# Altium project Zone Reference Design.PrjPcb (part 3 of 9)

## Sheet Load Driver Overview.SchDoc
size 431 x 279 mm; Date: Not shown in title block; ApprovedBy: Not shown in title block; CheckedBy: Not shown in title block; Author: Not shown in title block; CompanyName: Not shown in title block; Engineer: Not shown in title block; Organization: Not shown in title block; Address1: Not shown in title block; Address2: Not shown in title block; Address3: Not shown in title block; Address4: Not shown in title block; DocumentNumber: 1; Revision: Use project parameter SCH_Rev; SheetNumber: 13; SheetTotal: 30; PageSetup: Record=PageOptions¦CenterHorizontal=True¦CenterVertical=True¦PrintScale=1.00¦XCorrection=1.00¦YCorrection=1.00¦PrintKind=0¦BorderSize=5000000¦LeftOffset=0¦BottomOffset=0¦Orientation=2¦PaperLength=1000¦PaperWidth=1000¦Scale=100¦PaperSource=15¦PrintQuality=600¦MediaType=1¦DitherType=10¦PaperKind=Letter¦PrintScaleMode=1
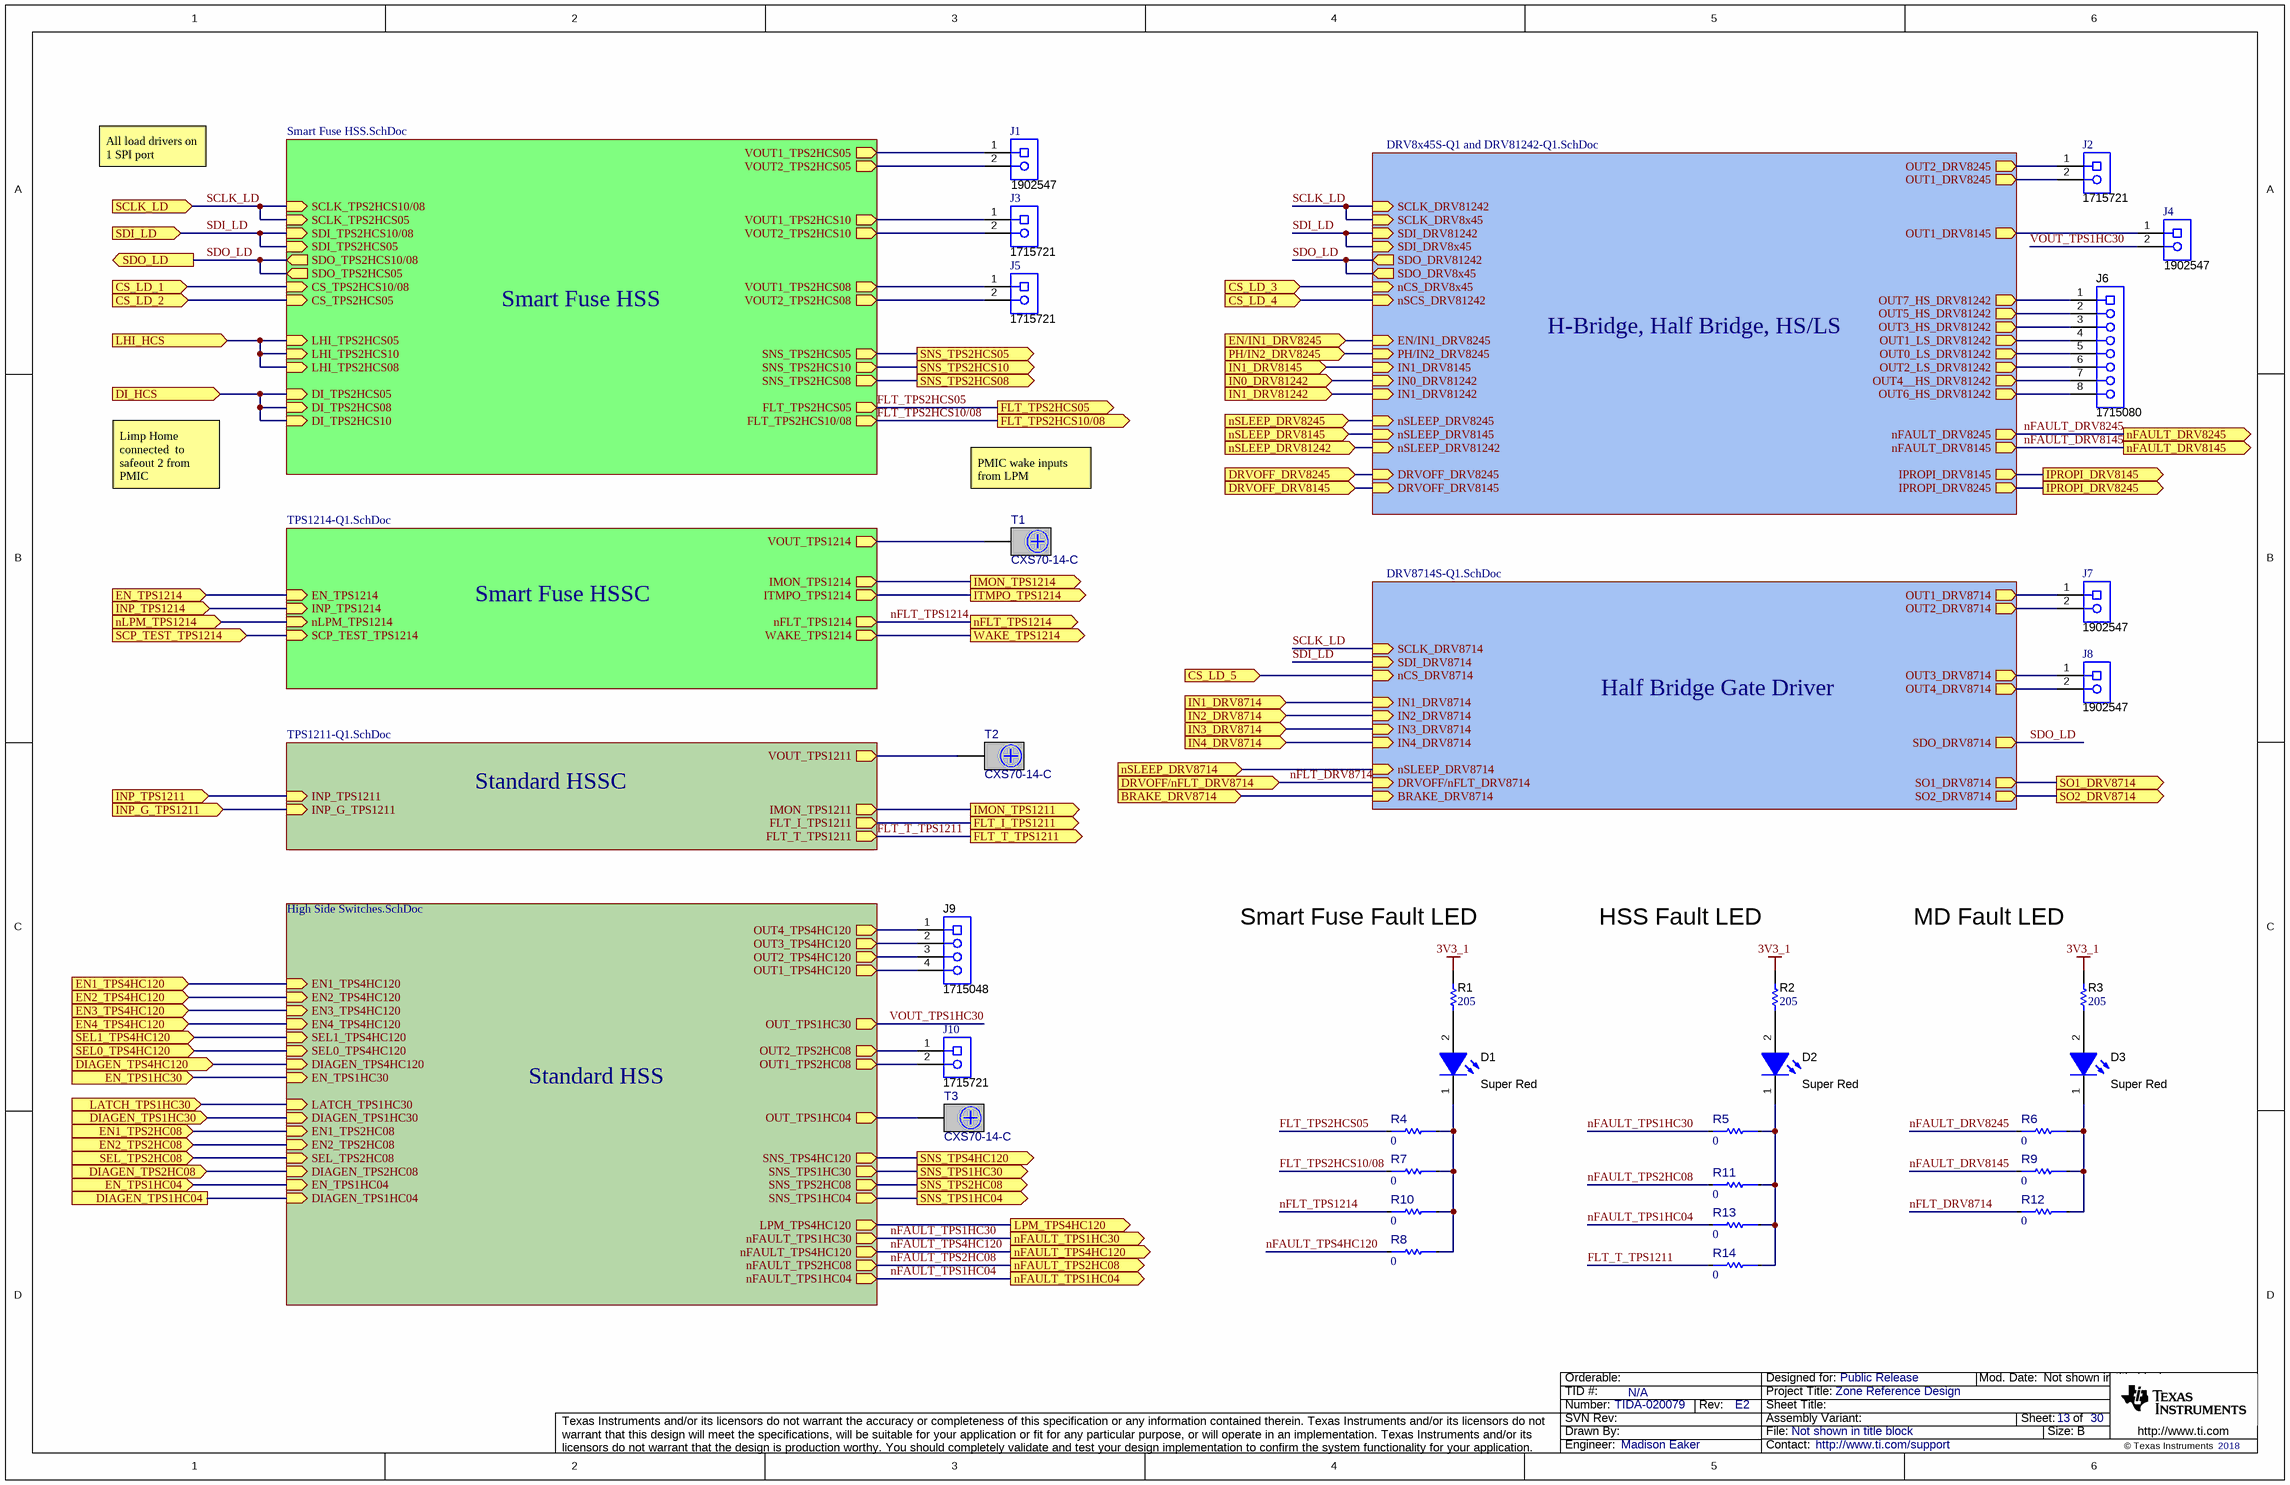
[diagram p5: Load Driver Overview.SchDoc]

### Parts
D1  value Super Red  [WL-SMCW_RED]  (hidden comment: 150060SS75000)
D2  value Super Red  [WL-SMCW_RED]  (hidden comment: 150060SS75000)
D3  value Super Red  [WL-SMCW_RED]  (hidden comment: 150060SS75000)
J1  1902547  [Phoenix_1902547]
J2  1715721  [PhoenixContact_1715721]
J3  1715721  [PhoenixContact_1715721]
J4  1902547  [Phoenix_1902547]
J5  1715721  [PhoenixContact_1715721]
J6  1715080  [Phoenix_1715080]
J7  1902547  [Phoenix_1902547]
J8  1902547  [Phoenix_1902547]
J9  1715048  [Phoenix_1715048]
J10  1715721  [PhoenixContact_1715721]
R1  ValueDisplayed: 205  [0603]  (hidden comment: RC0603FR-07205RL)
R2  ValueDisplayed: 205  [0603]  (hidden comment: RC0603FR-07205RL)
R3  ValueDisplayed: 205  [0603]  (hidden comment: RC0603FR-07205RL)
R4  value 0  [FP-ERJ-2GE0R00X_0402-MFG]  (hidden comment: ERJ-2GE0R00X)
R5  value 0  [FP-ERJ-2GE0R00X_0402-MFG]  (hidden comment: ERJ-2GE0R00X)
R6  value 0  [FP-ERJ-2GE0R00X_0402-MFG]  (hidden comment: ERJ-2GE0R00X)
R7  value 0  [FP-ERJ-2GE0R00X_0402-MFG]  (hidden comment: ERJ-2GE0R00X)
R8  value 0  [FP-ERJ-2GE0R00X_0402-MFG]  (hidden comment: ERJ-2GE0R00X)
R9  value 0  [FP-ERJ-2GE0R00X_0402-MFG]  (hidden comment: ERJ-2GE0R00X)
R10  value 0  [FP-ERJ-2GE0R00X_0402-MFG]  (hidden comment: ERJ-2GE0R00X)
R11  value 0  [FP-ERJ-2GE0R00X_0402-MFG]  (hidden comment: ERJ-2GE0R00X)
R12  value 0  [FP-ERJ-2GE0R00X_0402-MFG]  (hidden comment: ERJ-2GE0R00X)
R13  value 0  [FP-ERJ-2GE0R00X_0402-MFG]  (hidden comment: ERJ-2GE0R00X)
R14  value 0  [FP-ERJ-2GE0R00X_0402-MFG]  (hidden comment: ERJ-2GE0R00X)
T1  CXS70-14-C  [Panduit_CXS70-14-C]
T2  CXS70-14-C  [Panduit_CXS70-14-C]
T3  CXS70-14-C  [Panduit_CXS70-14-C]

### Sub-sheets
H-Bridge, Half Bridge, HS/LS = DRV8x45S-Q1 and DRV81242-Q1.SchDoc: DRVOFF_DRV8245 (in), nSLEEP_DRV8245 (in), EN/IN1_DRV8245 (in), PH/IN2_DRV8245 (in), IPROPI_DRV8245 (out), OUT1_DRV8245 (out), OUT2_DRV8245 (out), nFAULT_DRV8245 (out), DRVOFF_DRV8145 (in), nSLEEP_DRV8145 (in), IN1_DRV8145 (in), IPROPI_DRV8145 (out), OUT1_DRV8145 (out), nFAULT_DRV8145 (out), nSLEEP_DRV81242 (in), IN1_DRV81242 (in), SCLK_DRV81242 (in), SDI_DRV81242 (in), nSCS_DRV81242 (in), IN0_DRV81242 (in), OUT0_LS_DRV81242 (out), OUT1_LS_DRV81242 (out), OUT4__HS_DRV81242 (out), OUT6_HS_DRV81242 (out), OUT7_HS_DRV81242 (out), OUT5_HS_DRV81242 (out), OUT3_HS_DRV81242 (out), SDO_DRV81242 (out), OUT2_LS_DRV81242 (out), SDI_DRV8x45 (in), nCS_DRV8x45 (in), SCLK_DRV8x45 (in), SDO_DRV8x45 (out)
Half Bridge Gate Driver = DRV8714S-Q1.SchDoc: SDO_DRV8714 (out), SDI_DRV8714 (in), SCLK_DRV8714 (in), nCS_DRV8714 (in), nSLEEP_DRV8714 (in), IN1_DRV8714 (in), IN2_DRV8714 (in), IN3_DRV8714 (in), IN4_DRV8714 (in), DRVOFF/nFLT_DRV8714 (in), BRAKE_DRV8714 (in), OUT1_DRV8714 (out), OUT2_DRV8714 (out), OUT3_DRV8714 (out), OUT4_DRV8714 (out), SO1_DRV8714 (out), SO2_DRV8714 (out)
Smart Fuse HSS = Smart Fuse HSS.SchDoc: VOUT1_TPS2HCS10 (out), VOUT2_TPS2HCS10 (out), LHI_TPS2HCS10 (in), DI_TPS2HCS10 (in), SNS_TPS2HCS10 (out), FLT_TPS2HCS10/08 (out), VOUT1_TPS2HCS08 (out), VOUT2_TPS2HCS08 (out), LHI_TPS2HCS08 (in), DI_TPS2HCS08 (in), SNS_TPS2HCS08 (out), LHI_TPS2HCS05 (in), VOUT1_TPS2HCS05 (out), VOUT2_TPS2HCS05 (out), SNS_TPS2HCS05 (out), DI_TPS2HCS05 (in), FLT_TPS2HCS05 (out), SCLK_TPS2HCS10/08 (in), SDI_TPS2HCS10/08 (in), CS_TPS2HCS10/08 (in), SDO_TPS2HCS10/08 (out), SDI_TPS2HCS05 (in), SDO_TPS2HCS05 (out), CS_TPS2HCS05 (in), SCLK_TPS2HCS05 (in)
Smart Fuse HSSC = TPS1214-Q1.SchDoc: EN_TPS1214 (in), INP_TPS1214 (in), nLPM_TPS1214 (in), SCP_TEST_TPS1214 (in), WAKE_TPS1214 (out), VOUT_TPS1214 (out), IMON_TPS1214 (out), ITMPO_TPS1214 (out), nFLT_TPS1214 (out)
Standard HSS = High Side Switches.SchDoc: EN_TPS1HC30 (in), DIAGEN_TPS1HC30 (in), LATCH_TPS1HC30 (in), nFAULT_TPS1HC30 (out), SNS_TPS1HC30 (out), OUT_TPS1HC30 (out), EN1_TPS4HC120 (in), EN2_TPS4HC120 (in), EN3_TPS4HC120 (in), EN4_TPS4HC120 (in), DIAGEN_TPS4HC120 (in), SEL0_TPS4HC120 (in), SEL1_TPS4HC120 (in), nFAULT_TPS4HC120 (out), LPM_TPS4HC120 (out), SNS_TPS4HC120 (out), OUT1_TPS4HC120 (out), OUT2_TPS4HC120 (out), OUT3_TPS4HC120 (out), OUT4_TPS4HC120 (out), EN1_TPS2HC08 (in), EN2_TPS2HC08 (in), DIAGEN_TPS2HC08 (in), SEL_TPS2HC08 (in), OUT1_TPS2HC08 (out), OUT2_TPS2HC08 (out), SNS_TPS2HC08 (out), EN_TPS1HC04 (in), DIAGEN_TPS1HC04 (in), OUT_TPS1HC04 (out), SNS_TPS1HC04 (out), nFAULT_TPS2HC08 (out), nFAULT_TPS1HC04 (out)
Standard HSSC = TPS1211-Q1.SchDoc: INP_TPS1211 (in), INP_G_TPS1211 (in), FLT_T_TPS1211 (out), FLT_I_TPS1211 (out), VOUT_TPS1211 (out), IMON_TPS1211 (out)

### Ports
BRAKE_DRV8714 (in), CS_LD_1 (in), CS_LD_2 (in), CS_LD_3 (in), CS_LD_4 (in), CS_LD_5 (in), DI_HCS (in), DIAGEN_TPS1HC04 (in), DIAGEN_TPS1HC30 (in), DIAGEN_TPS2HC08 (in), DIAGEN_TPS4HC120 (in), DRVOFF/nFLT_DRV8714 (in), DRVOFF_DRV8145 (in), DRVOFF_DRV8245 (in), EN1_TPS2HC08 (in), EN1_TPS4HC120 (in), EN2_TPS2HC08 (in), EN2_TPS4HC120 (in), EN3_TPS4HC120 (in), EN4_TPS4HC120 (in), EN/IN1_DRV8245 (in), EN_TPS1HC04 (in), EN_TPS1HC30 (in), EN_TPS1214 (in), FLT_I_TPS1211 (out), FLT_T_TPS1211 (out), FLT_TPS2HCS05 (out), FLT_TPS2HCS10/08 (out), IMON_TPS1211 (out), IMON_TPS1214 (out), IN0_DRV81242 (in), IN1_DRV8145 (in), IN1_DRV8714 (in), IN1_DRV81242 (in), IN2_DRV8714 (in), IN3_DRV8714 (in), IN4_DRV8714 (in), INP_G_TPS1211 (in), INP_TPS1211 (in), INP_TPS1214 (in), IPROPI_DRV8145 (out), IPROPI_DRV8245 (out), ITMPO_TPS1214 (out), LATCH_TPS1HC30 (in), LHI_HCS (in), LPM_TPS4HC120 (out), nFAULT_DRV8145 (out), nFAULT_DRV8245 (out), nFAULT_TPS1HC04 (out), nFAULT_TPS1HC30 (out), nFAULT_TPS2HC08 (out), nFAULT_TPS4HC120 (out), nFLT_TPS1214 (out), nLPM_TPS1214 (in), nSLEEP_DRV8145 (in), nSLEEP_DRV8245 (in), nSLEEP_DRV8714 (in), nSLEEP_DRV81242 (in), PH/IN2_DRV8245 (in), SCLK_LD (in), SCP_TEST_TPS1214 (in), SDI_LD (in), SDO_LD (out), SEL0_TPS4HC120 (in), SEL1_TPS4HC120 (in), SEL_TPS2HC08 (in), SNS_TPS1HC04 (out), SNS_TPS1HC30 (out), SNS_TPS2HC08 (out), SNS_TPS2HCS05 (out), SNS_TPS2HCS08 (out), SNS_TPS2HCS10 (out), SNS_TPS4HC120 (out), SO1_DRV8714 (out), SO2_DRV8714 (out), WAKE_TPS1214 (out)

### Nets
3V3_1: R1.2 R2.2 R3.2
ADC2_AIN0: port SNS_TPS2HCS05, sheet Smart Fuse HSS/SNS_TPS2HCS05
ADC2_AIN1: port SNS_TPS2HCS10, sheet Smart Fuse HSS/SNS_TPS2HCS10
ADC2_AIN2: port SNS_TPS2HCS08, sheet Smart Fuse HSS/SNS_TPS2HCS08
ADC2_AIN5: port IMON_TPS1211, sheet Standard HSSC/IMON_TPS1211
ADC3_AIN0: port SNS_TPS1HC04, sheet Standard HSS/SNS_TPS1HC04
ADC3_AIN1: port SNS_TPS2HC08, sheet Standard HSS/SNS_TPS2HC08
ADC3_AIN2: port SNS_TPS1HC30, sheet Standard HSS/SNS_TPS1HC30
ADC3_AIN3: port SNS_TPS4HC120, sheet Standard HSS/SNS_TPS4HC120
ADC4_AIN0: port IPROPI_DRV8145, sheet H-Bridge, Half Bridge, HS/LS/IPROPI_DRV8145
ADC4_AIN1: port IPROPI_DRV8245, sheet H-Bridge, Half Bridge, HS/LS/IPROPI_DRV8245
ADC4_AIN2: port SO1_DRV8714, sheet Half Bridge Gate Driver/SO1_DRV8714
ADC4_AIN3: port SO2_DRV8714, sheet Half Bridge Gate Driver/SO2_DRV8714
BRAKE_DRV8714: port BRAKE_DRV8714, sheet Half Bridge Gate Driver/BRAKE_DRV8714
CS_LD_1: port CS_LD_1, sheet Smart Fuse HSS/CS_TPS2HCS10/08
CS_LD_2: port CS_LD_2, sheet Smart Fuse HSS/CS_TPS2HCS05
CS_LD_4: port CS_LD_4, sheet H-Bridge, Half Bridge, HS/LS/nSCS_DRV81242
DI_HCS: port DI_HCS, sheet Smart Fuse HSS/DI_TPS2HCS10, sheet Smart Fuse HSS/DI_TPS2HCS08, sheet Smart Fuse HSS/DI_TPS2HCS05
DIAGEN_TPS1HC04: port DIAGEN_TPS1HC04, sheet Standard HSS/DIAGEN_TPS1HC04
DIAGEN_TPS1HC30: port DIAGEN_TPS1HC30, sheet Standard HSS/DIAGEN_TPS1HC30
DIAGEN_TPS2HC08: port DIAGEN_TPS2HC08, sheet Standard HSS/DIAGEN_TPS2HC08
DIAGEN_TPS4HC120: port DIAGEN_TPS4HC120, sheet Standard HSS/DIAGEN_TPS4HC120
DRVOFF_DRV8145: port DRVOFF_DRV8245, port DRVOFF_DRV8145, sheet H-Bridge, Half Bridge, HS/LS/DRVOFF_DRV8245, sheet H-Bridge, Half Bridge, HS/LS/DRVOFF_DRV8145
EN1_TPS2HC08: port EN1_TPS2HC08, sheet Standard HSS/EN1_TPS2HC08
EN1_TPS4HC120: port EN1_TPS4HC120, sheet Standard HSS/EN1_TPS4HC120
EN2_TPS2HC08: port EN2_TPS2HC08, sheet Standard HSS/EN2_TPS2HC08
EN2_TPS4HC120: port EN2_TPS4HC120, sheet Standard HSS/EN2_TPS4HC120
EN3_TPS4HC120: port EN3_TPS4HC120, sheet Standard HSS/EN3_TPS4HC120
EN4_TPS4HC120: port EN4_TPS4HC120, sheet Standard HSS/EN4_TPS4HC120
EN/IN1_DRV8245: port EN/IN1_DRV8245, sheet H-Bridge, Half Bridge, HS/LS/EN/IN1_DRV8245
EN_TPS1HC04: port EN_TPS1HC04, sheet Standard HSS/EN_TPS1HC04
EN_TPS1HC30: port EN_TPS1HC30, sheet Standard HSS/EN_TPS1HC30
EN_TPS1214: port EN_TPS1214, sheet Smart Fuse HSSC/EN_TPS1214
EPWM0_B: port PH/IN2_DRV8245, sheet H-Bridge, Half Bridge, HS/LS/PH/IN2_DRV8245
EPWM1_A: port IN0_DRV81242, sheet H-Bridge, Half Bridge, HS/LS/IN0_DRV81242
EPWM1_B: port IN1_DRV81242, sheet H-Bridge, Half Bridge, HS/LS/IN1_DRV81242
EPWM2_A: port IN1_DRV8145, sheet H-Bridge, Half Bridge, HS/LS/IN1_DRV8145
EPWM3_A: port IN1_DRV8714, sheet Half Bridge Gate Driver/IN1_DRV8714
EPWM3_B: port IN2_DRV8714, sheet Half Bridge Gate Driver/IN2_DRV8714
EPWM4_A: port IN3_DRV8714, sheet Half Bridge Gate Driver/IN3_DRV8714
EPWM4_B: port IN4_DRV8714, sheet Half Bridge Gate Driver/IN4_DRV8714
EPWM_15A: port SCP_TEST_TPS1214, sheet Smart Fuse HSSC/SCP_TEST_TPS1214
FLT_I_TPS1211: port FLT_I_TPS1211, sheet Standard HSSC/FLT_I_TPS1211
FLT_T_TPS1211: R14.2 ; port FLT_T_TPS1211, sheet Standard HSSC/FLT_T_TPS1211
FLT_TPS2HCS05: R4.2 ; port FLT_TPS2HCS05, sheet Smart Fuse HSS/FLT_TPS2HCS05
FLT_TPS2HCS10/08: R7.2 ; port FLT_TPS2HCS10/08, sheet Smart Fuse HSS/FLT_TPS2HCS10/08
GPIO79: port INP_TPS1214, sheet Smart Fuse HSSC/INP_TPS1214
GPIO107: port nLPM_TPS1214, sheet Smart Fuse HSSC/nLPM_TPS1214
IMON: port IMON_TPS1214, sheet Smart Fuse HSSC/IMON_TPS1214
INP_G_TPS1211: port INP_G_TPS1211, sheet Standard HSSC/INP_G_TPS1211
INP_TPS1211: port INP_TPS1211, sheet Standard HSSC/INP_TPS1211
ITMPO: port ITMPO_TPS1214, sheet Smart Fuse HSSC/ITMPO_TPS1214
LATCH_TPS1HC30: port LATCH_TPS1HC30, sheet Standard HSS/LATCH_TPS1HC30
LHI_HCS: port LHI_HCS, sheet Smart Fuse HSS/LHI_TPS2HCS10, sheet Smart Fuse HSS/LHI_TPS2HCS08, sheet Smart Fuse HSS/LHI_TPS2HCS05
LPM_TPS4HC120: port LPM_TPS4HC120, sheet Standard HSS/LPM_TPS4HC120
nCS: port CS_LD_3, sheet H-Bridge, Half Bridge, HS/LS/nCS_DRV8x45
nFAULT_DRV8145: R6.2 R9.2 ; port nFAULT_DRV8245, port nFAULT_DRV8145, sheet H-Bridge, Half Bridge, HS/LS/nFAULT_DRV8245, sheet H-Bridge, Half Bridge, HS/LS/nFAULT_DRV8145  [also labelled nFAULT_DRV8245]
nFAULT_TPS1HC04: R13.2 ; port nFAULT_TPS1HC04, sheet Standard HSS/nFAULT_TPS1HC04
nFAULT_TPS1HC30: R5.2 ; port nFAULT_TPS1HC30, sheet Standard HSS/nFAULT_TPS1HC30
nFAULT_TPS2HC08: R11.2 ; port nFAULT_TPS2HC08, sheet Standard HSS/nFAULT_TPS2HC08
nFAULT_TPS4HC120: R8.2 ; port nFAULT_TPS4HC120, sheet Standard HSS/nFAULT_TPS4HC120
nFLT_DRV8714: R12.2 ; port DRVOFF/nFLT_DRV8714, sheet Half Bridge Gate Driver/DRVOFF/nFLT_DRV8714
nFLT_TPS1214: R10.2 ; port nFLT_TPS1214, sheet Smart Fuse HSSC/nFLT_TPS1214  [project net FLT/]
nSLEEP_DRV81242: port nSLEEP_DRV8245, port nSLEEP_DRV8145, port nSLEEP_DRV81242, port nSLEEP_DRV8714, sheet Half Bridge Gate Driver/nSLEEP_DRV8714, sheet H-Bridge, Half Bridge, HS/LS/nSLEEP_DRV8245, sheet H-Bridge, Half Bridge, HS/LS/nSLEEP_DRV8145, sheet H-Bridge, Half Bridge, HS/LS/nSLEEP_DRV81242
OUT0_LS_DRV81242: J6.5 ; sheet H-Bridge, Half Bridge, HS/LS/OUT0_LS_DRV81242
OUT1_DRV8145: J4.1 ; sheet H-Bridge, Half Bridge, HS/LS/OUT1_DRV8145
OUT1_DRV8245: J2.2 ; sheet H-Bridge, Half Bridge, HS/LS/OUT1_DRV8245
OUT1_DRV8714: J7.1 ; sheet Half Bridge Gate Driver/OUT1_DRV8714
OUT1_LS_DRV81242: J6.4 ; sheet H-Bridge, Half Bridge, HS/LS/OUT1_LS_DRV81242
OUT1_TPS2HC08: J10.2 ; sheet Standard HSS/OUT1_TPS2HC08
OUT1_TPS4HC120: J9.4 ; sheet Standard HSS/OUT1_TPS4HC120
OUT2_DRV8245: J2.1 ; sheet H-Bridge, Half Bridge, HS/LS/OUT2_DRV8245
OUT2_DRV8714: J7.2 ; sheet Half Bridge Gate Driver/OUT2_DRV8714
OUT2_LS_DRV81242: J6.6 ; sheet H-Bridge, Half Bridge, HS/LS/OUT2_LS_DRV81242
OUT2_TPS2HC08: J10.1 ; sheet Standard HSS/OUT2_TPS2HC08
OUT2_TPS4HC120: J9.3 ; sheet Standard HSS/OUT2_TPS4HC120
OUT3_DRV8714: J8.1 ; sheet Half Bridge Gate Driver/OUT3_DRV8714
OUT3_HS_DRV81242: J6.3 ; sheet H-Bridge, Half Bridge, HS/LS/OUT3_HS_DRV81242
OUT3_TPS4HC120: J9.2 ; sheet Standard HSS/OUT3_TPS4HC120
OUT4__HS_DRV81242: J6.7 ; sheet H-Bridge, Half Bridge, HS/LS/OUT4__HS_DRV81242
OUT4_DRV8714: J8.2 ; sheet Half Bridge Gate Driver/OUT4_DRV8714
OUT4_TPS4HC120: J9.1 ; sheet Standard HSS/OUT4_TPS4HC120
OUT5_HS_DRV81242: J6.2 ; sheet H-Bridge, Half Bridge, HS/LS/OUT5_HS_DRV81242
OUT6_HS_DRV81242: J6.8 ; sheet H-Bridge, Half Bridge, HS/LS/OUT6_HS_DRV81242
OUT7_HS_DRV81242: J6.1 ; sheet H-Bridge, Half Bridge, HS/LS/OUT7_HS_DRV81242
OUT_TPS1HC04: T3.1 ; sheet Standard HSS/OUT_TPS1HC04
P15_TCAL9539: port SEL0_TPS4HC120, sheet Standard HSS/SEL0_TPS4HC120
P16_TCAL9539: port SEL1_TPS4HC120, sheet Standard HSS/SEL1_TPS4HC120
P23_TXE8116: port SEL_TPS2HC08, sheet Standard HSS/SEL_TPS2HC08
SCLK_LD: port SCLK_LD, sheet Half Bridge Gate Driver/SCLK_DRV8714, sheet H-Bridge, Half Bridge, HS/LS/SCLK_DRV81242, sheet H-Bridge, Half Bridge, HS/LS/SCLK_DRV8x45, sheet Smart Fuse HSS/SCLK_TPS2HCS10/08, sheet Smart Fuse HSS/SCLK_TPS2HCS05  [project net SCLK]
SDI_LD: port SDI_LD, sheet Half Bridge Gate Driver/SDI_DRV8714, sheet H-Bridge, Half Bridge, HS/LS/SDI_DRV81242, sheet H-Bridge, Half Bridge, HS/LS/SDI_DRV8x45, sheet Smart Fuse HSS/SDI_TPS2HCS10/08, sheet Smart Fuse HSS/SDI_TPS2HCS05  [project net SDI]
SDO_LD: port SDO_LD, sheet Half Bridge Gate Driver/SDO_DRV8714, sheet H-Bridge, Half Bridge, HS/LS/SDO_DRV81242, sheet H-Bridge, Half Bridge, HS/LS/SDO_DRV8x45, sheet Smart Fuse HSS/SDO_TPS2HCS10/08, sheet Smart Fuse HSS/SDO_TPS2HCS05
SPI7_CS5: port CS_LD_5, sheet Half Bridge Gate Driver/nCS_DRV8714
SRC: T1.1 ; sheet Smart Fuse HSSC/VOUT_TPS1214
VOUT1_TPS2HCS05: J1.1 ; sheet Smart Fuse HSS/VOUT1_TPS2HCS05
VOUT1_TPS2HCS08: J5.1 ; sheet Smart Fuse HSS/VOUT1_TPS2HCS08
VOUT1_TPS2HCS10: J3.1 ; sheet Smart Fuse HSS/VOUT1_TPS2HCS10
VOUT2_TPS2HCS05: J1.2 ; sheet Smart Fuse HSS/VOUT2_TPS2HCS05
VOUT2_TPS2HCS08: J5.2 ; sheet Smart Fuse HSS/VOUT2_TPS2HCS08
VOUT2_TPS2HCS10: J3.2 ; sheet Smart Fuse HSS/VOUT2_TPS2HCS10
VOUT_TPS1HC30: J4.2 ; sheet Standard HSS/OUT_TPS1HC30
VOUT_TPS1211: T2.1 ; sheet Standard HSSC/VOUT_TPS1211
WAKE: port WAKE_TPS1214, sheet Smart Fuse HSSC/WAKE_TPS1214
NetD1_1: D1.1(K) R4.1 R7.1 R8.1 R10.1
NetD1_2: D1.2(A) R1.1
NetD2_1: D2.1(K) R5.1 R11.1 R13.1 R14.1
NetD2_2: D2.2(A) R2.1
NetD3_1: D3.1(K) R6.1 R9.1 R12.1
NetD3_2: D3.2(A) R3.1

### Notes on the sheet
- All load drivers on 1 SPI port
- Limp Home connected  to safeout 2 from PMIC
- PMIC wake inputs from LPM
- Smart Fuse Fault LED
- HSS Fault LED
- MD Fault LED

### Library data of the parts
D1-D3 = CMP-0002893-1: LED, Super Red, SMD; Manufacturer: Wurth Elektronik; Io_A: 20mA; Value1: W; U/M: EA; Vf_V: 1.9V; Type: AlInGaP
J1 J4 J7 J8 = CMP-0055527-1: Terminal Block, 9.52mm, 2x1, R/A, TH; Manufacturer: Phoenix Contact; Cert_VDE: Y; CNHeader: FALSE; Current_A: 32A; Gender: Female; Voltage_V: 1kV; Row_Count: 1; Pitch_mm: 9.52; CT: TRUE
J2 J3 J5 J10 = CMP-0055471-1: Terminal Block, 5.08 mm, 2x1, TH; Manufacturer: Phoenix Contact; Cert_VDE: Y; CNHeader: FALSE; Current_A: 17.5A; Green_Lifecycle: Not Set; Gender: Female; Cert_CULUS: N; Green_REACh: Incomplete; Voltage_V: 400V; Row_Count: 1; Pitch_mm: 5.08; ContactFinish: Tin; CT: TRUE
J6 = CMP-0055522-1: Terminal Block, 5mm, 8 Pos, TH; Manufacturer: Phoenix Contact; CNHeader: FALSE; Current_A: 17.5A; Gender: Female; Cert_CULUS: Y; Row_Count: 1; Pitch_mm: 5; CT: TRUE
J9 = CMP-0055526-1: Terminal Block, 5mm, 4x1, R/A,TH; Manufacturer: Phoenix Contact; Cert_VDE: Y; CNHeader: FALSE; Current_A: 17.5A; Gender: Female; Voltage_V: 400V; Row_Count: 1; Pitch_mm: 5; CT: TRUE
R1-R3 = CMP-0022904-5: RES, 205, 1%, 0.1 W, 0603; Manufacturer: Yageo; Power_W: 100mW; TempCo: 100 ppm/C; Value_Code: 205R; Value: 205; EIA_Code: E96; SizeX_mm: 1.6; SizeY_mm: 0.8; SizeZ_mm: 1; Value2: 0.1W; SizeArea_mm2: 1.28; AEC Qualified: N; VDC_V: 75V; AEC Category: Q200; SizeAreaWB_mm2: 4.68
R4-R14 = CMP-0002710-1: 0 Ohms Jumper Chip Resistor 0402 (1005 Metric) Automotive AEC-Q200 Thick Film; Manufacturer: Panasonic; SizeZ_mm: 0.4mm; AEC Qualified: Yes; AEC Grade: Grade 0; Power: 100mW
T1-T3 = CMP-0075010-2: Terminal 70A Lug; Manufacturer: Panduit; CompType: Screw Terminal; CT: False; Green_Lifecycle: Not Set; Green_REACh: Incomplete

## Sheet High Side Switches.SchDoc
size 431 x 279 mm; Date: Not shown in title block; ApprovedBy: Not shown in title block; CheckedBy: Not shown in title block; Author: Not shown in title block; CompanyName: Not shown in title block; Engineer: Not shown in title block; Organization: Not shown in title block; Address1: Not shown in title block; Address2: Not shown in title block; Address3: Not shown in title block; Address4: Not shown in title block; DocumentNumber: 1; Revision: Use project parameter SCH_Rev; SheetNumber: 16; SheetTotal: 30; PageSetup: Record=PageOptions¦CenterHorizontal=True¦CenterVertical=True¦PrintScale=1.00¦XCorrection=1.00¦YCorrection=1.00¦PrintKind=0¦BorderSize=5000000¦LeftOffset=0¦BottomOffset=0¦Orientation=2¦PaperLength=1000¦PaperWidth=1000¦Scale=100¦PaperSource=15¦PrintQuality=600¦MediaType=1¦DitherType=10¦PaperKind=Letter¦PrintScaleMode=1
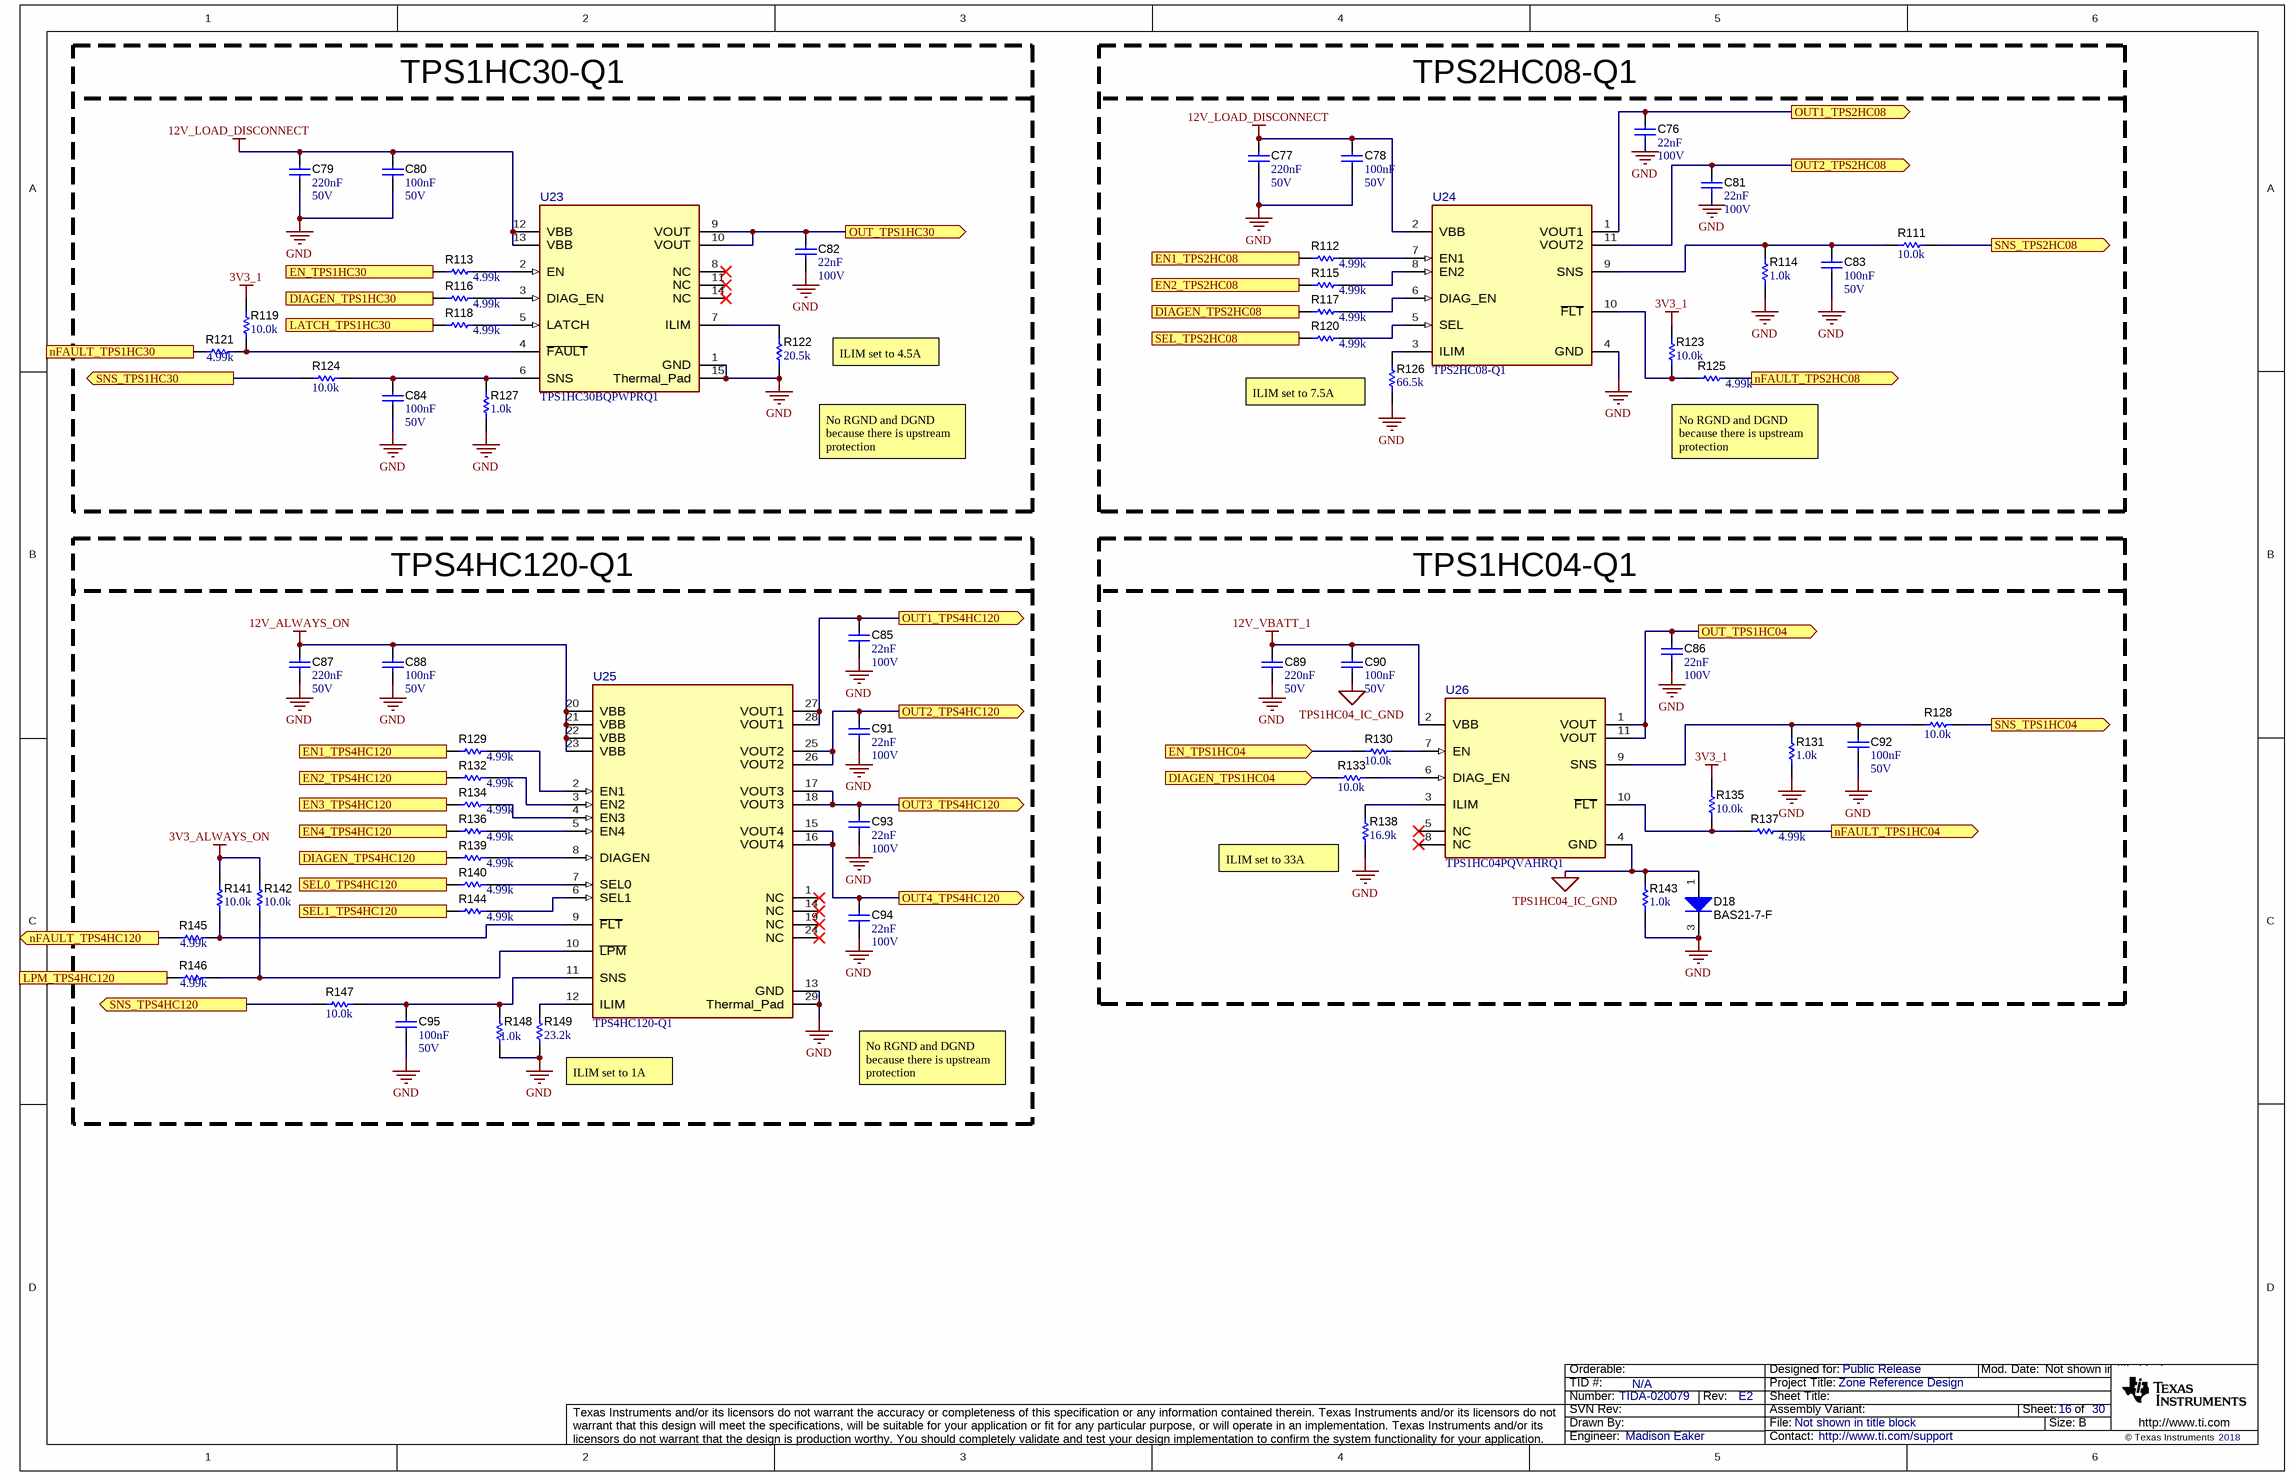
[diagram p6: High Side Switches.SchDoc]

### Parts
C76  Cap_F: 22nF  VDC_V: 100V  [0603]  (hidden comment: CGA3E2X7R2A223K080AA)
C77  Cap_F: 220nF  VDC_V: 50V  [0603]  (hidden comment: GCJ188R71H224KA01D)
C78  Cap_F: 100nF  VDC_V: 50V  [0603]  (hidden comment: 06035C104KAZ2A)
C79  Cap_F: 220nF  VDC_V: 50V  [0603]  (hidden comment: GCJ188R71H224KA01D)
C80  Cap_F: 100nF  VDC_V: 50V  [0603]  (hidden comment: 06035C104KAZ2A)
C81  Cap_F: 22nF  VDC_V: 100V  [0603]  (hidden comment: CGA3E2X7R2A223K080AA)
C82  Cap_F: 22nF  VDC_V: 100V  [0603]  (hidden comment: CGA3E2X7R2A223K080AA)
C83  Cap_F: 100nF  VDC_V: 50V  [0603]  (hidden comment: 06035C104KAZ2A)
C84  Cap_F: 100nF  VDC_V: 50V  [0603]  (hidden comment: 06035C104KAZ2A)
C85  Cap_F: 22nF  VDC_V: 100V  [0603]  (hidden comment: CGA3E2X7R2A223K080AA)
C86  Cap_F: 22nF  VDC_V: 100V  [0603]  (hidden comment: CGA3E2X7R2A223K080AA)
C87  Cap_F: 220nF  VDC_V: 50V  [0603]  (hidden comment: GCJ188R71H224KA01D)
C88  Cap_F: 100nF  VDC_V: 50V  [0603]  (hidden comment: 06035C104KAZ2A)
C89  Cap_F: 220nF  VDC_V: 50V  [0603]  (hidden comment: GCJ188R71H224KA01D)
C90  Cap_F: 100nF  VDC_V: 50V  [0603]  (hidden comment: 06035C104KAZ2A)
C91  Cap_F: 22nF  VDC_V: 100V  [0603]  (hidden comment: CGA3E2X7R2A223K080AA)
C92  Cap_F: 100nF  VDC_V: 50V  [0603]  (hidden comment: 06035C104KAZ2A)
C93  Cap_F: 22nF  VDC_V: 100V  [0603]  (hidden comment: CGA3E2X7R2A223K080AA)
C94  Cap_F: 22nF  VDC_V: 100V  [0603]  (hidden comment: CGA3E2X7R2A223K080AA)
C95  Cap_F: 100nF  VDC_V: 50V  [0603]  (hidden comment: 06035C104KAZ2A)
D18  BAS21-7-F  [SOT-23L]
R111  ValueDisplayed: 10.0k  [0603]  (hidden comment: RMCF0603FT10K0)
R112  ValueDisplayed: 4.99k  [0603]  (hidden comment: CRCW06034K99FKEA)
R113  ValueDisplayed: 4.99k  [0603]  (hidden comment: CRCW06034K99FKEA)
R114  ValueDisplayed: 1.0k  [0603]  (hidden comment: ESR03EZPJ102)
R115  ValueDisplayed: 4.99k  [0603]  (hidden comment: CRCW06034K99FKEA)
R116  ValueDisplayed: 4.99k  [0603]  (hidden comment: CRCW06034K99FKEA)
R117  ValueDisplayed: 4.99k  [0603]  (hidden comment: CRCW06034K99FKEA)
R118  ValueDisplayed: 4.99k  [0603]  (hidden comment: CRCW06034K99FKEA)
R119  ValueDisplayed: 10.0k  [0603]  (hidden comment: RMCF0603FT10K0)
R120  ValueDisplayed: 4.99k  [0603]  (hidden comment: CRCW06034K99FKEA)
R121  ValueDisplayed: 4.99k  [0603]  (hidden comment: CRCW06034K99FKEA)
R122  ValueDisplayed: 20.5k  [0603]  (hidden comment: CRCW060320K5FKEA)
R123  ValueDisplayed: 10.0k  [0603]  (hidden comment: RMCF0603FT10K0)
R124  ValueDisplayed: 10.0k  [0603]  (hidden comment: RMCF0603FT10K0)
R125  ValueDisplayed: 4.99k  [0603]  (hidden comment: CRCW06034K99FKEA)
R126  ValueDisplayed: 66.5k  [0603]  (hidden comment: CRCW060366K5FKEA)
R127  ValueDisplayed: 1.0k  [0603]  (hidden comment: ESR03EZPJ102)
R128  ValueDisplayed: 10.0k  [0603]  (hidden comment: RMCF0603FT10K0)
R129  ValueDisplayed: 4.99k  [0603]  (hidden comment: CRCW06034K99FKEA)
R130  ValueDisplayed: 10.0k  [TNPW0603]  (hidden comment: TNPW060310K0BEEA)
R131  ValueDisplayed: 1.0k  [0603]  (hidden comment: ESR03EZPJ102)
R132  ValueDisplayed: 4.99k  [0603]  (hidden comment: CRCW06034K99FKEA)
R133  ValueDisplayed: 10.0k  [TNPW0603]  (hidden comment: TNPW060310K0BEEA)
R134  ValueDisplayed: 4.99k  [0603]  (hidden comment: CRCW06034K99FKEA)
R135  ValueDisplayed: 10.0k  [0603]  (hidden comment: RMCF0603FT10K0)
R136  ValueDisplayed: 4.99k  [0603]  (hidden comment: CRCW06034K99FKEA)
R137  ValueDisplayed: 4.99k  [0603]  (hidden comment: CRCW06034K99FKEA)
R138  ValueDisplayed: 16.9k  [0603]  (hidden comment: CRCW060316K9FKEA)
R139  ValueDisplayed: 4.99k  [0603]  (hidden comment: CRCW06034K99FKEA)
R140  ValueDisplayed: 4.99k  [0603]  (hidden comment: CRCW06034K99FKEA)
R141  ValueDisplayed: 10.0k  [0603]  (hidden comment: RMCF0603FT10K0)
R142  ValueDisplayed: 10.0k  [0603]  (hidden comment: RMCF0603FT10K0)
R143  ValueDisplayed: 1.0k  [0603]  (hidden comment: ESR03EZPJ102)
R144  ValueDisplayed: 4.99k  [0603]  (hidden comment: CRCW06034K99FKEA)
R145  ValueDisplayed: 4.99k  [0603]  (hidden comment: CRCW06034K99FKEA)
R146  ValueDisplayed: 4.99k  [0603]  (hidden comment: CRCW06034K99FKEA)
R147  ValueDisplayed: 10.0k  [0603]  (hidden comment: RMCF0603FT10K0)
R148  ValueDisplayed: 1.0k  [0603]  (hidden comment: ESR03EZPJ102)
R149  ValueDisplayed: 23.2k  [0603]  (hidden comment: CRCW060323K2FKEA)
U23  TPS1HC30BQPWPRQ1  [PWP0014C-MFG]
U24  TPS2HC08-Q1  [VAH0011C-MFG]
U25  TPS4HC120-Q1  [DGQ0028A-MFG]
U26  TPS1HC04PQVAHRQ1  [VAH0011B-MFG]

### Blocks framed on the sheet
TPS1HC30-Q1: C79 C80 C82 C84 R113 R116 R118 R119 R121 R122 R124 R127 U23
TPS2HC08-Q1: C76-C78 C81 C83 R111 R112 R114 R115 R117 R120 R123 R125 R126 U24
TPS4HC120-Q1: C85 C87 C88 C91 C93-C95 R129 R132 R134 R136 R139-R142 R144-R149 U25
TPS1HC04-Q1: C86 C89 C90 C92 D18 R128 R130 R131 R133 R135 R137 R138 R143 U26

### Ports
DIAGEN_TPS1HC04 (in), DIAGEN_TPS1HC30 (in), DIAGEN_TPS2HC08 (in), DIAGEN_TPS4HC120 (in), EN1_TPS2HC08 (in), EN1_TPS4HC120 (in), EN2_TPS2HC08 (in), EN2_TPS4HC120 (in), EN3_TPS4HC120 (in), EN4_TPS4HC120 (in), EN_TPS1HC04 (in), EN_TPS1HC30 (in), LATCH_TPS1HC30 (in), LPM_TPS4HC120 (out), nFAULT_TPS1HC04 (out), nFAULT_TPS1HC30 (out), nFAULT_TPS2HC08 (out), nFAULT_TPS4HC120 (out), OUT1_TPS2HC08 (out), OUT1_TPS4HC120 (out), OUT2_TPS2HC08 (out), OUT2_TPS4HC120 (out), OUT3_TPS4HC120 (out), OUT4_TPS4HC120 (out), OUT_TPS1HC04 (out), OUT_TPS1HC30 (out), SEL0_TPS4HC120 (in), SEL1_TPS4HC120 (in), SEL_TPS2HC08 (in), SNS_TPS1HC04 (out), SNS_TPS1HC30 (out), SNS_TPS2HC08 (out), SNS_TPS4HC120 (out)

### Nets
3V3_1: R119.2 R123.2 R135.2
3V3_ALWAYS_ON: R141.2 R142.2
12V_ALWAYS_ON: C87.1 C88.1 U25.20(VBB) U25.21(VBB) U25.22(VBB) U25.23(VBB)
12V_LOAD_DISCONNECT: C77.1 C78.1 C79.1 C80.1 U23.12(VBB) U23.13(VBB) U24.2(VBB)  [project net VS]
12V_VBATT_1: C89.1 C90.1 U26.2(VBB)
GND: C76.2 C77.2 C78.2 C79.2 C80.2 C81.2 C82.2 C83.2 C84.2 C85.2 C86.2 C87.2 C88.2 C89.2 C91.2 C92.2 C93.2 C94.2 C95.2 D18.3(K) R114.1 R122.1 R126.1 R127.1 R131.1 R138.2 R143.1 R148.1 R149.1 U23.1(GND) U23.15(Thermal_Pad) U24.4(GND) U25.13(GND) U25.29(Thermal_Pad)
TPS1HC04_IC_GND: C90.2 D18.1(A) R143.2 U26.4(GND)
ADC3_AIN0: R128.1 ; port SNS_TPS1HC04
ADC3_AIN1: R111.1 ; port SNS_TPS2HC08
ADC3_AIN2: R124.2 ; port SNS_TPS1HC30
ADC3_AIN3: R147.2 ; port SNS_TPS4HC120
DIAGEN_TPS1HC04: R133.1 ; port DIAGEN_TPS1HC04
DIAGEN_TPS1HC30: R116.1 ; port DIAGEN_TPS1HC30
DIAGEN_TPS2HC08: R117.1 ; port DIAGEN_TPS2HC08
DIAGEN_TPS4HC120: R139.1 ; port DIAGEN_TPS4HC120
EN1_TPS2HC08: R112.1 ; port EN1_TPS2HC08
EN1_TPS4HC120: R129.1 ; port EN1_TPS4HC120
EN2_TPS2HC08: R115.1 ; port EN2_TPS2HC08
EN2_TPS4HC120: R132.1 ; port EN2_TPS4HC120
EN3_TPS4HC120: R134.1 ; port EN3_TPS4HC120
EN4_TPS4HC120: R136.1 ; port EN4_TPS4HC120
EN_TPS1HC04: R130.1 ; port EN_TPS1HC04
EN_TPS1HC30: R113.1 ; port EN_TPS1HC30
LATCH_TPS1HC30: R118.1 ; port LATCH_TPS1HC30
LPM_TPS4HC120: R146.1 ; port LPM_TPS4HC120
nFAULT_TPS1HC04: R137.2 ; port nFAULT_TPS1HC04
nFAULT_TPS1HC30: R121.1 ; port nFAULT_TPS1HC30
nFAULT_TPS2HC08: R125.2 ; port nFAULT_TPS2HC08
nFAULT_TPS4HC120: R145.1 ; port nFAULT_TPS4HC120
OUT1_TPS2HC08: C76.1 U24.1(VOUT1) ; port OUT1_TPS2HC08
OUT1_TPS4HC120: C85.1 U25.27(VOUT1) U25.28(VOUT1) ; port OUT1_TPS4HC120
OUT2_TPS2HC08: C81.1 U24.11(VOUT2) ; port OUT2_TPS2HC08
OUT2_TPS4HC120: C91.1 U25.25(VOUT2) U25.26(VOUT2) ; port OUT2_TPS4HC120
OUT3_TPS4HC120: C93.1 U25.17(VOUT3) U25.18(VOUT3) ; port OUT3_TPS4HC120
OUT4_TPS4HC120: C94.1 U25.15(VOUT4) U25.16(VOUT4) ; port OUT4_TPS4HC120
OUT_TPS1HC04: C86.1 U26.1(VOUT) U26.11(VOUT) ; port OUT_TPS1HC04
P15_TCAL9539: R140.1 ; port SEL0_TPS4HC120
P16_TCAL9539: R144.1 ; port SEL1_TPS4HC120
P23_TXE8116: R120.1 ; port SEL_TPS2HC08
VOUT_TPS1HC30: C82.1 U23.9(VOUT) U23.10(VOUT) ; port OUT_TPS1HC30
NetC83_1: C83.1 R111.2 R114.2 U24.9(SNS)
NetC84_1: C84.1 R124.1 R127.2 U23.6(SNS)
NetC92_1: C92.1 R128.2 R131.2 U26.9(SNS)
NetC95_1: C95.1 R147.1 R148.2 U25.11(SNS)
NetR112_2: R112.2 U24.7(EN1)
NetR113_2: R113.2 U23.2(EN)
NetR115_2: R115.2 U24.8(EN2)
NetR116_2: R116.2 U23.3(DIAG_EN)
NetR117_2: R117.2 U24.6(DIAG_EN)
NetR118_2: R118.2 U23.5(LATCH)
NetR119_1: R119.1 R121.2 U23.4(~{FAULT})
NetR120_2: R120.2 U24.5(SEL)
NetR122_2: R122.2 U23.7(ILIM)
NetR123_1: R123.1 R125.1 U24.10(~{FLT})
NetR126_2: R126.2 U24.3(ILIM)
NetR129_2: R129.2 U25.2(EN1)
NetR130_2: R130.2 U26.7(EN)
NetR132_2: R132.2 U25.3(EN2)
NetR133_2: R133.2 U26.6(DIAG_EN)
NetR134_2: R134.2 U25.4(EN3)
NetR135_1: R135.1 R137.1 U26.10(~{FLT})
NetR136_2: R136.2 U25.5(EN4)
NetR138_1: R138.1 U26.3(ILIM)
NetR139_2: R139.2 U25.8(DIAGEN)
NetR140_2: R140.2 U25.7(SEL0)
NetR141_1: R141.1 R145.2 U25.9(~{FLT})
NetR142_1: R142.1 R146.2 U25.10(~{LPM})
NetR144_2: R144.2 U25.6(SEL1)
NetR149_2: R149.2 U25.12(ILIM)

Not connected (* = marked no-connect by the designer): U23 8(NC)* 11(NC)* 14(NC)*; U25 1(NC)* 14(NC)* 19(NC)* 24(NC)*; U26 5(NC)* 8(NC)*

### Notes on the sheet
- ILIM set to 4.5A
- ILIM set to 7.5A
- No RGND and DGND because there is upstream protection
- (near R138) ILIM set to 33A
- (near R149) ILIM set to 1A

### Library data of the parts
C76 C81 C82 C85 C86 C91 C93 C94 = CMP-0007086-4: CAP, CERM, 0.022 uF, 100 V, +/- 10%, X7R, AEC-Q200 Grade 1, 0603; Manufacturer: TDK; TaMin_C: -55°C; ESR_ohm: 83.542m; Polarized: N; SizeAreaWB_mm2: 4.68; Value1: 0.083542 ohm; U/M: EA; TaMax_C: 125°C; SizeZ_mm: 1; SizeX_mm: 1.6; SizeY_mm: 0.8; SizeArea_mm2: 1.28; AEC Qualified: Y; IRMS_A: 609.312mA; AEC Category: Q200
C77 C79 C87 C89 = CMP-0079579-1: CAP, CERM, 0.22 µF, 50 V,+/- 10%, X7R, AEC-Q200 Grade 1, 0603; Manufacturer: MuRata; SizeAreaWB_mm2: 4.68; SizeArea_mm2: 1.28; AEC Qualified: Y; AEC Category: Q200; Value: 0.22uF; TaMax_C: 125°C; SizeZ_mm: 1; Polarized: N; TaMin_C: -55°C; SizeY_mm: 0.8; U/M: EA; SizeX_mm: 1.6; ValueDisplayed: 0.22µF
C78 C80 C83 C84 C88 C90 C92 C95 = CMP-0079095-1: CAP, CERM, 0.1 µF, 50 V,+/- 10%, X7R, AEC-Q200 Grade 1, 0603; Manufacturer: AVX; SizeAreaWB_mm2: 4.68; SizeArea_mm2: 1.28; AEC Qualified: Y; AEC Category: Q200; Value: 0.1uF; TaMax_C: 125°C; SizeZ_mm: 1; Polarized: N; TaMin_C: -55°C; SizeY_mm: 0.8; U/M: EA; SizeX_mm: 1.6; ValueDisplayed: 0.1µF
D18 = CMP-0076901-2: Diode, Switching, 200 V, 0.2 A, SOT-23; Manufacturer: Diodes Inc.; TJmax_C: 150°C; SizeZ_mm: 1.1; AEC Category: Q101; Green_REACh: Passed; Value1: 0.2A; SizeY_mm: 3.0; Io_A: 200mA; Value2: 1.25V; SizeX_mm: 2.5; Green_Lifecycle: Active; Vr_V: 200V; SizeArea_mm2: 7.5; Value: 200V; SizeAreaWB_mm2: 14.0
R111 R119 R123 R124 R128 R135 R141 R142 R147 = CMP-0023341-2: RES, 10.0 k, 1%, 0.1 W, AEC-Q200 Grade 0, 0603; Manufacturer: Stackpole Electronics Inc; Power_W: 100mW; TempCo: 100 ppm/C; Value_Code: 10k0; U/M: EA; Value: 10.0k; EIA_Code: E96; Res_ohm: 10k; SizeX_mm: 1.6; SizeY_mm: 0.8; SizeZ_mm: 1; Value2: 0.1W; SizeArea_mm2: 1.28; AEC Qualified: Y; VDC_V: 75V; AEC Grade: 0; AEC Category: Q200
R112 R113 R115-R118 R120 R121 R125 R129 R132 R134 R136 R137 R139 R140 R144-R146 = CMP-0022458-4: RES, 4.99 k, 1%, 0.1 W, AEC-Q200 Grade 0, 0603; Manufacturer: Vishay-Dale; Power_W: 100mW; TempCo: 100 ppm/C; Value_Code: 4k99; Value: 4.99k; EIA_Code: E96; SizeX_mm: 1.6; SizeY_mm: 0.8; SizeZ_mm: 1; Value2: 0.1W; SizeArea_mm2: 1.28; AEC Qualified: Y; VDC_V: 75V; AEC Category: Q200; AEC Grade: 0
R114 R127 R131 R143 R148 = CMP-0084244-1: RES, 1.0 k, 5%, 0.25 W, AEC-Q200 Grade 0, 0603; Manufacturer: Rohm; Power_W: 250mW; TempCo: 200 ppm/C; SizeAreaWB_mm2: 4.68; Value_Code: 1k00; Value: 1.0k; EIA_Code: E24; Res_ohm: 1k; SizeX_mm: 1.6; SizeY_mm: 0.8; SizeZ_mm: 1; Value2: 0.25W; SizeArea_mm2: 1.28; AEC Qualified: Y; AEC Grade: 0; AEC Category: Q200
R122 = CMP-0022205-4: RES, 20.5 k, 1%, 0.1 W, AEC-Q200 Grade 0, 0603; Manufacturer: Vishay-Dale; Power_W: 100mW; TempCo: 100 ppm/C; Value_Code: 20k5; Value: 20.5k; EIA_Code: E96; SizeX_mm: 1.6; SizeY_mm: 0.8; SizeZ_mm: 1; Value2: 0.1W; SizeArea_mm2: 1.28; AEC Qualified: Y; VDC_V: 75V; AEC Category: Q200; AEC Grade: 0
R126 = CMP-0022548-4: RES, 66.5 k, 1%, 0.1 W, AEC-Q200 Grade 0, 0603; Manufacturer: Vishay-Dale; Power_W: 100mW; TempCo: 100 ppm/C; Value_Code: 66k5; Value: 66.5k; EIA_Code: E96; SizeX_mm: 1.6; SizeY_mm: 0.8; SizeZ_mm: 1; Value2: 0.1W; SizeArea_mm2: 1.28; AEC Qualified: Y; VDC_V: 75V; AEC Category: Q200; AEC Grade: 0
R130 R133 = CMP-0025686-1: RES, 10.0 k, 0.1%, 0.1 W, AEC-Q200 Grade 1, 0603; Manufacturer: Vishay-Dale; Power_W: 100mW; TempCo: 25 ppm/C; Value_Code: 10k0; U/M: EA; Value: 10.0k; EIA_Code: E192; Res_ohm: 10k; SizeX_mm: 1.6; SizeY_mm: 0.85; SizeZ_mm: 0.55; Value2: 0.1W; SizeArea_mm2: 1.36; AEC Qualified: Y; VDC_V: 75V; AEC Grade: 1; AEC Category: Q200
R138 = CMP-0022081-1: RES, 16.9 k, 1%, 0.1 W, 0603; Manufacturer: Vishay-Dale; Power_W: 100mW; TempCo: 100 ppm/C; Value_Code: 16k9; U/M: EA; Value: 16.9k; EIA_Code: E96; SizeX_mm: 1.6; SizeY_mm: 0.8; SizeZ_mm: 1; Value2: 0.1W; SizeArea_mm2: 1.28; VDC_V: 75V; AEC Category: Q200
R149 = CMP-0022228-4: RES, 23.2 k, 1%, 0.1 W, AEC-Q200 Grade 0, 0603; Manufacturer: Vishay-Dale; Power_W: 100mW; TempCo: 100 ppm/C; Value_Code: 23k2; Value: 23.2k; EIA_Code: E96; SizeX_mm: 1.6; SizeY_mm: 0.8; SizeZ_mm: 1; Value2: 0.1W; SizeArea_mm2: 1.28; AEC Qualified: Y; VDC_V: 75V; AEC Category: Q200; AEC Grade: 0
U23 = CMP-0094747-1: 30-mΩ, 5-A Single-Channel Smart High-Side Switch, HTSSOP14; Manufacturer: Texas Instruments; Nominal Supply Current: 1.6mA; Min Supply Voltage: 2.6V; TaMax_C: +125°C; TaMin_C: -40°C; SizeZ_mm: 1.2mm; AEC Grade: Grade 1; Turn On Delay Time: 40us; Standoff Height: 0.05mm; TJmax_C: +150°C; Max Supply Voltage: 28V; Turn Off Delay Time: 30us; AEC Qualified: Yes; Number Of Outputs: 1
U24 = CMP-0123761-1: Manufacturer: Texas Instruments; SizeZ_mm: 1mm; Standoff Height: 0mm
U25 = CMP-0038451-2: 1A, 120-mΩ Quad-Channel Smart High-Side Switch; Manufacturer: Texas Instruments; SizeZ_mm: 1.1mm; AEC Qualified: Yes; AEC Grade: Grade 1; Max Supply Voltage: 18V; Min Supply Voltage: 6V; Nominal Supply Current: 1.3-4.9mA; Number Of Outputs: 4; Standoff Height: 0mm; TaMax_C: +125°C; TaMin_C: -40°C; TJmax_C: +150°C; AEC Category: Q200; CompType: IC
U26 = CMP-0127210-1: Manufacturer: Texas Instruments; SizeZ_mm: 1mm; Standoff Height: 0mm

## Sheet DRV8714S-Q1.SchDoc
size 431 x 279 mm; Date: Not shown in title block; ApprovedBy: Not shown in title block; CheckedBy: Not shown in title block; Author: Not shown in title block; CompanyName: Not shown in title block; Engineer: Not shown in title block; Organization: Not shown in title block; Address1: Not shown in title block; Address2: Not shown in title block; Address3: Not shown in title block; Address4: Not shown in title block; DocumentNumber: 1; Revision: Use project parameter SCH_Rev; SheetNumber: 17; SheetTotal: 30; PageSetup: Record=PageOptions¦CenterHorizontal=True¦CenterVertical=True¦PrintScale=1.00¦XCorrection=1.00¦YCorrection=1.00¦PrintKind=0¦BorderSize=5000000¦LeftOffset=0¦BottomOffset=0¦Orientation=2¦PaperLength=1000¦PaperWidth=1000¦Scale=100¦PaperSource=15¦PrintQuality=600¦MediaType=1¦DitherType=10¦PaperKind=Letter¦PrintScaleMode=1
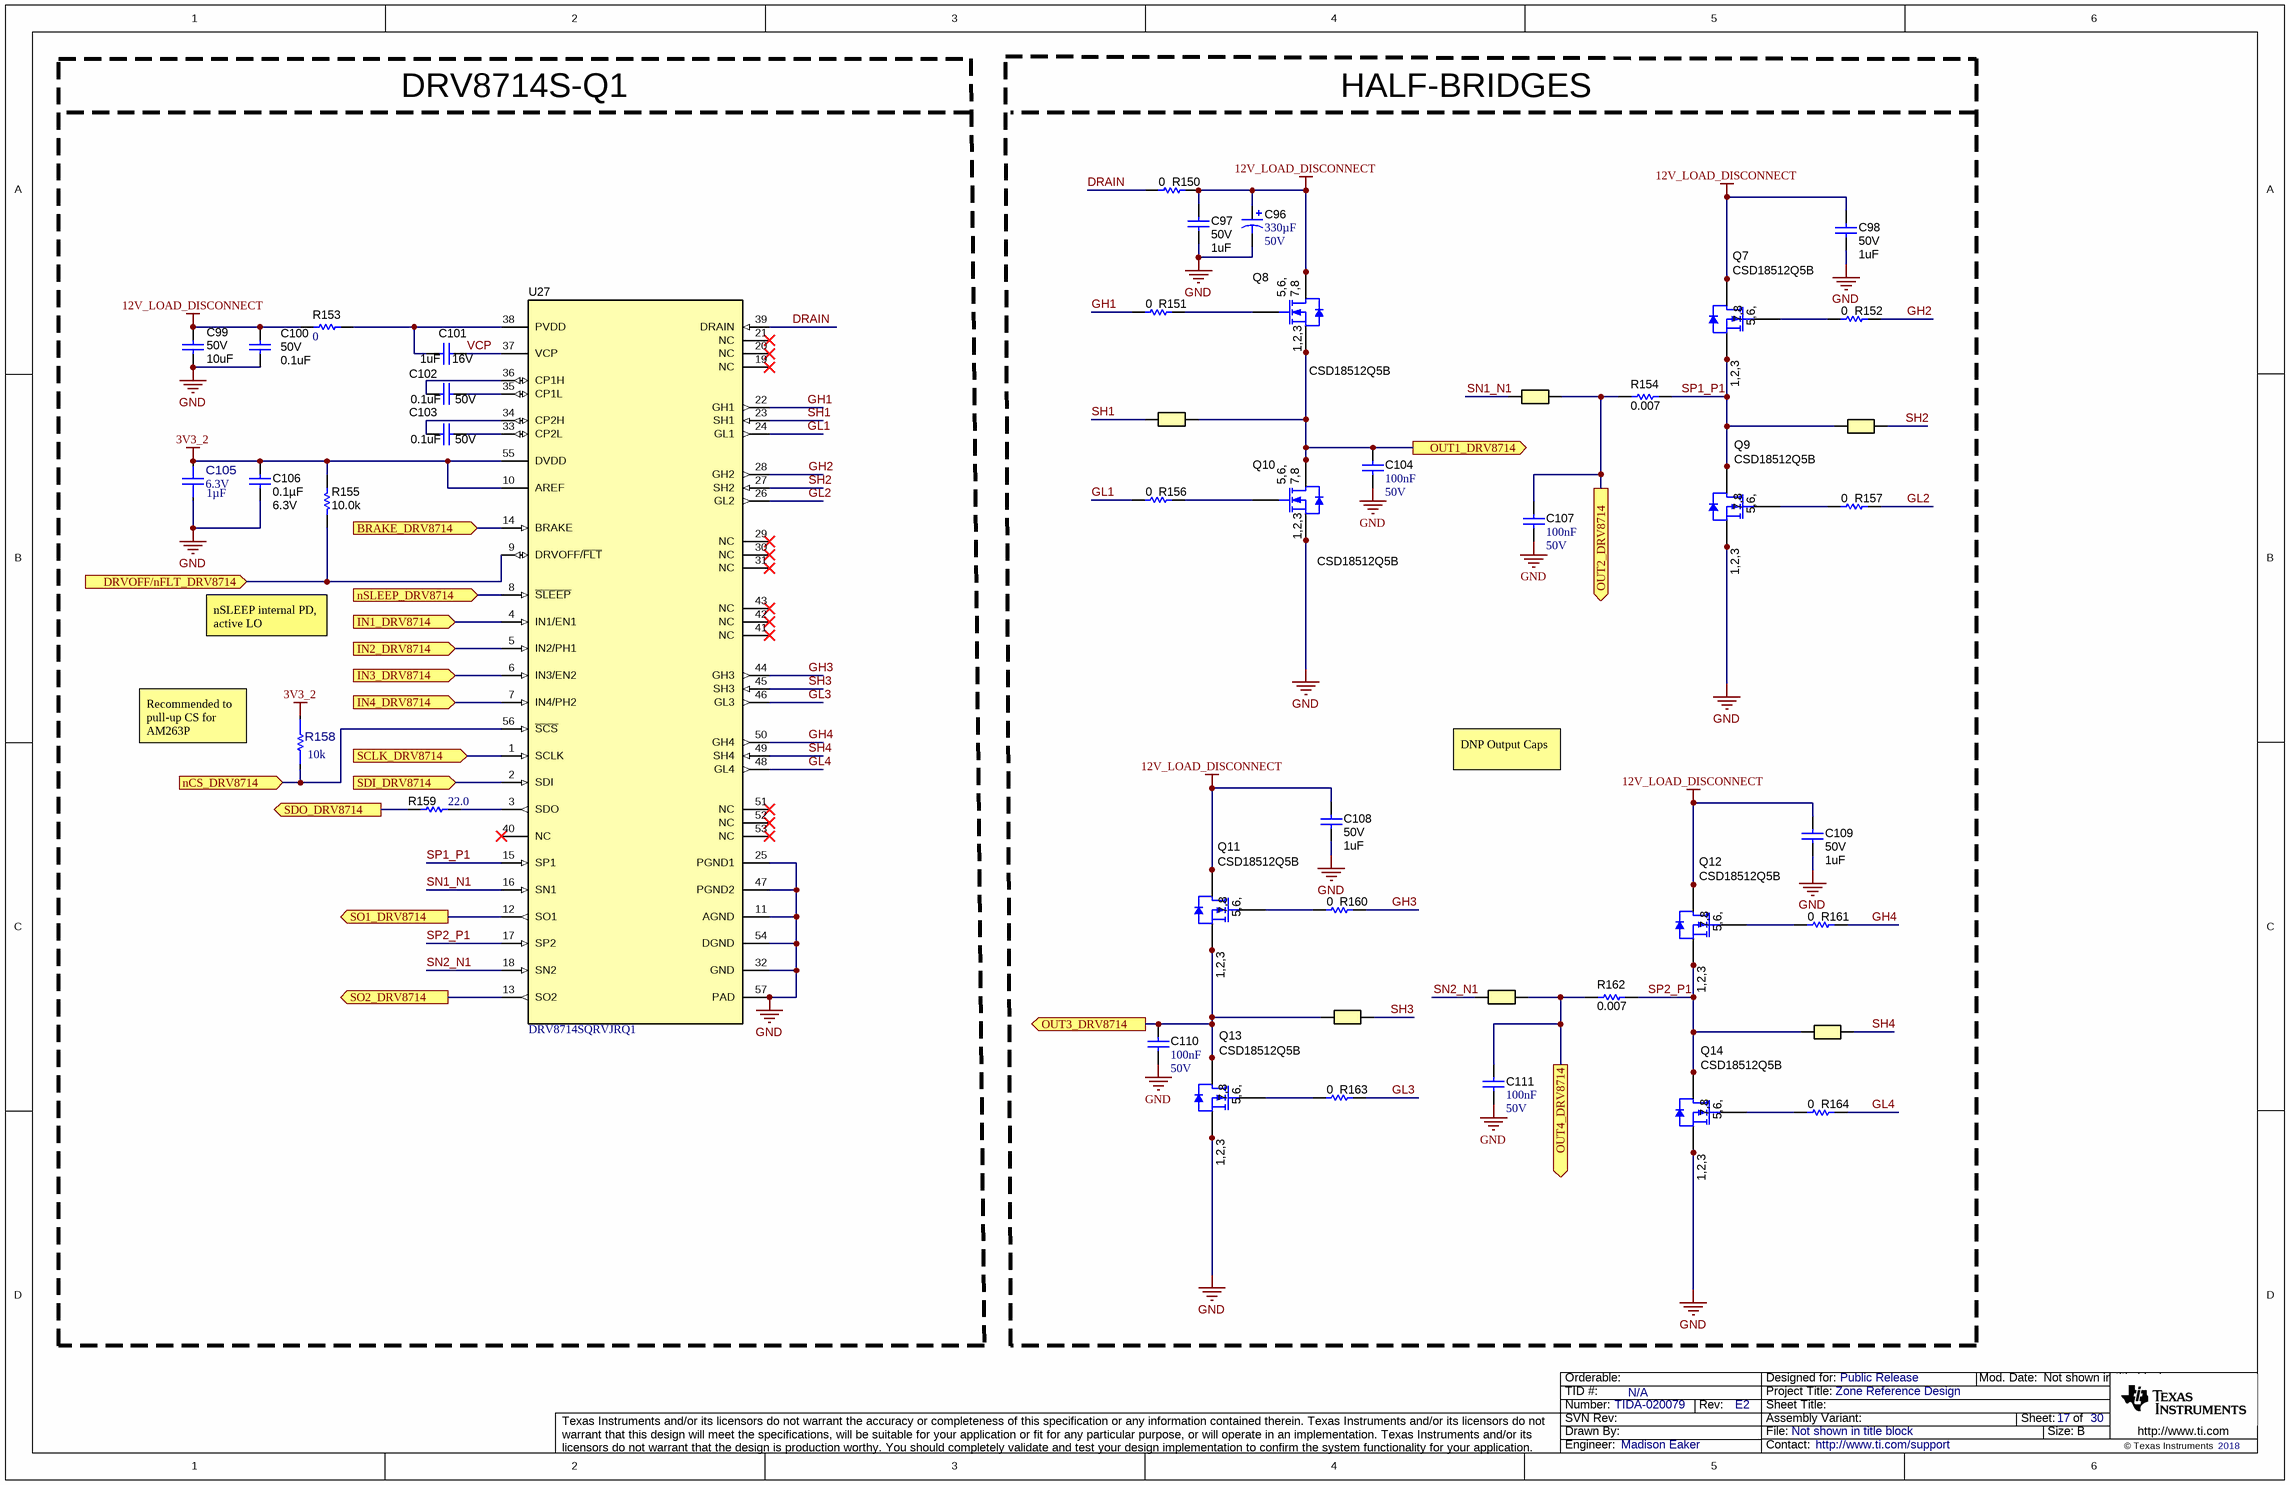
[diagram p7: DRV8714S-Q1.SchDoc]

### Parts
C96  ValueDisplayed: 330µF  VDC_V: 50V  [SM_RADIAL_G]  (hidden comment: EEE-FT1H331AP)
C97  VDC_V: 50V  ValueDisplayed: 1uF  [0805L]  (hidden comment: 885012207103)
C98  VDC_V: 50V  ValueDisplayed: 1uF  [0805L]  (hidden comment: 885012207103)
C99  VDC_V: 50V  ValueDisplayed: 10uF  [1210_280]  (hidden comment: CGA6P3X7S1H106K250AB)
C100  VDC_V: 50V  ValueDisplayed: 0.1uF  [0603L]  (hidden comment: 885012206095)
C101  VDC_V: 16V  ValueDisplayed: 1uF  [0603L]  (hidden comment: 885012206052)
C102  VDC_V: 50V  ValueDisplayed: 0.1uF  [0603L]  (hidden comment: 885012206095)
C103  VDC_V: 50V  ValueDisplayed: 0.1uF  [0603L]  (hidden comment: 885012206095)
C104  Cap_F: 100nF  VDC_V: 50V  [0603]  (hidden comment: 06035C104KAZ2A)
C105  VDC_V: 6.3V  Cap_F: 1µF  [FP-C0603X105J9RACAUTO_0603-MFG]  (hidden comment: C0603X105J9RACAUTO)
C106  ValueDisplayed: 0.1µF  VDC_V: 6.3V  [0603L]  (hidden comment: C0603C104K9RAC7867)
C107  Cap_F: 100nF  VDC_V: 50V  [0603]  (hidden comment: 06035C104KAZ2A)
C108  VDC_V: 50V  ValueDisplayed: 1uF  [0805L]  (hidden comment: 885012207103)
C109  VDC_V: 50V  ValueDisplayed: 1uF  [0805L]  (hidden comment: 885012207103)
C110  Cap_F: 100nF  VDC_V: 50V  [0603]  (hidden comment: 06035C104KAZ2A)
C111  Cap_F: 100nF  VDC_V: 50V  [0603]  (hidden comment: 06035C104KAZ2A)
NT1  Net-Tie  [Net-Tie_20milWide_60milLong]  (value not drawn)  (net tie, no BOM)
NT2  Net-Tie  [Net-Tie_20milWide_60milLong]  (value not drawn)  (net tie, no BOM)
NT3  Net-Tie  [Net-Tie_20milWide_60milLong]  (value not drawn)  (net tie, no BOM)
NT4  Net-Tie  [Net-Tie_20milWide_60milLong]  (value not drawn)  (net tie, no BOM)
NT5  Net-Tie  [Net-Tie_20milWide_60milLong]  (value not drawn)  (net tie, no BOM)
NT6  Net-Tie  [Net-Tie_20milWide_60milLong]  (value not drawn)  (net tie, no BOM)
Q7  CSD18512Q5B  [DNK0008A]
Q8  CSD18512Q5B  [DNK0008A]
Q9  CSD18512Q5B  [DNK0008A]
Q10  CSD18512Q5B  [DNK0008A]
Q11  CSD18512Q5B  [DNK0008A]
Q12  CSD18512Q5B  [DNK0008A]
Q13  CSD18512Q5B  [DNK0008A]
Q14  CSD18512Q5B  [DNK0008A]
R150  value 0  [0603L]  (hidden comment: Resistor)
R151  value 0  [0603L]  (hidden comment: Resistor)
R152  value 0  [0603L]  (hidden comment: Resistor)
R153  ValueDisplayed: 0  [0402]  (hidden comment: CRCW04020000Z0ED)
R154  ValueDisplayed: 0.007  [WSHM2818]  (hidden comment: WSHM28187L000FEA)
R155  ValueDisplayed: 10.0k  [0603L]  (hidden comment: ERA-3ARW103V)
R156  value 0  [0603L]  (hidden comment: Resistor)
R157  value 0  [0603L]  (hidden comment: Resistor)
R158  value 10k  [FP-RC0402JR-0710KL_0402-MFG]  (hidden comment: RC0402JR-0710KL)
R159  ValueDisplayed: 22.0  [0201]  (hidden comment: RC0201FR-0722RL)
R160  value 0  [0603L]  (hidden comment: Resistor)
R161  value 0  [0603L]  (hidden comment: Resistor)
R162  ValueDisplayed: 0.007  [WSHM2818]  (hidden comment: WSHM28187L000FEA)
R163  value 0  [0603L]  (hidden comment: Resistor)
R164  value 0  [0603L]  (hidden comment: Resistor)
U27  DRV8714SQRVJRQ1  [RVJ0056A]

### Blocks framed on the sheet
HALF-BRIDGES: C96-C98 C104 C107-C111 NT1-NT6 Q7-Q14 R150-R152 R154 R156 R157 R160-R164
DRV8714S-Q1: C99-C103 C105 C106 R153 R155 R158 R159 U27

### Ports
BRAKE_DRV8714 (in), DRVOFF/nFLT_DRV8714 (in), IN1_DRV8714 (in), IN2_DRV8714 (in), IN3_DRV8714 (in), IN4_DRV8714 (in), nCS_DRV8714 (in), nSLEEP_DRV8714 (in), OUT1_DRV8714 (out), OUT2_DRV8714 (out), OUT3_DRV8714 (out), OUT4_DRV8714 (out), SCLK_DRV8714 (in), SDI_DRV8714 (in), SDO_DRV8714 (out), SO1_DRV8714 (out), SO2_DRV8714 (out)

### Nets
3V3_2: C105.2 C106.2 R155.1 R158.1 U27.10(AREF) U27.55(DVDD)
12V_LOAD_DISCONNECT: C96.1(+) C97.1 C98.1 C99.1 C100.1 C108.1 C109.1 Q7.5(D) Q7.6(D) Q7.7(D) Q7.8(D) Q7.9(D) Q8.5(D) Q8.6(D) Q8.7(D) Q8.8(D) Q8.9(D) Q11.5(D) Q11.6(D) Q11.7(D) Q11.8(D) Q11.9(D) Q12.5(D) Q12.6(D) Q12.7(D) Q12.8(D) Q12.9(D) R150.1 R153.1  [project net VS]
GND: C96.2(-) C97.2 C98.2 C99.2 C100.2 C104.2 C105.1 C106.1 C107.2 C108.2 C109.2 C110.2 C111.2 Q9.1(S) Q9.2(S) Q9.3(S) Q10.1(S) Q10.2(S) Q10.3(S) Q13.1(S) Q13.2(S) Q13.3(S) Q14.1(S) Q14.2(S) Q14.3(S) U27.11(AGND) U27.25(PGND1) U27.32(GND) U27.47(PGND2) U27.54(DGND) U27.57(PAD)
ADC4_AIN2: U27.12(SO1) ; port SO1_DRV8714
ADC4_AIN3: U27.13(SO2) ; port SO2_DRV8714
BRAKE_DRV8714: U27.14(BRAKE) ; port BRAKE_DRV8714
DRAIN: R150.2 U27.39(DRAIN)  [project net DRAIN_17]
EPWM3_A: U27.4(IN1/EN1) ; port IN1_DRV8714
EPWM3_B: U27.5(IN2/PH1) ; port IN2_DRV8714
EPWM4_A: U27.6(IN3/EN2) ; port IN3_DRV8714
EPWM4_B: U27.7(IN4/PH2) ; port IN4_DRV8714
GH1: R151.2 U27.22(GH1)  [project net GH1_17]
GH2: R152.1 U27.28(GH2)  [project net GH2_17]
GH3: R160.1 U27.44(GH3)  [project net GH3_17]
GH4: R161.1 U27.50(GH4)  [project net GH4_17]
GL1: R156.2 U27.24(GL1)  [project net GL1_17]
GL2: R157.1 U27.26(GL2)  [project net GL2_17]
GL3: R163.1 U27.46(GL3)  [project net GL3_17]
GL4: R164.1 U27.48(GL4)  [project net GL4_17]
nFLT_DRV8714: R155.2 U27.9(DRVOFF/~{FLT}) ; port DRVOFF/nFLT_DRV8714
nSLEEP_DRV81242: U27.8(~{SLEEP}) ; port nSLEEP_DRV8714
OUT1_DRV8714: C104.1 NT2.2 Q8.1(S) Q8.2(S) Q8.3(S) Q10.5(D) Q10.6(D) Q10.7(D) Q10.8(D) Q10.9(D) ; port OUT1_DRV8714
OUT2_DRV8714: C107.1 NT1.1 R154.2 ; port OUT2_DRV8714
OUT3_DRV8714: C110.1 NT5.2 Q11.1(S) Q11.2(S) Q11.3(S) Q13.5(D) Q13.6(D) Q13.7(D) Q13.8(D) Q13.9(D) ; port OUT3_DRV8714
OUT4_DRV8714: C111.1 NT4.1 R162.2 ; port OUT4_DRV8714
SCLK: U27.1(SCLK) ; port SCLK_DRV8714
SDI: U27.2(SDI) ; port SDI_DRV8714
SDO_LD: R159.1 ; port SDO_DRV8714
SH1: NT2.1 U27.23(SH1)  [project net SH1_17]
SH2: NT3.1 U27.27(SH2)  [project net SH2_17]
SH3: NT5.1 U27.45(SH3)  [project net SH3_17]
SH4: NT6.1 U27.49(SH4)  [project net SH4_17]
SN1_N1: NT1.2 U27.16(SN1)  [project net SN1_N1_17]
SN2_N1: NT4.2 U27.18(SN2)  [project net SN2_N1_17]
SP1_P1: NT3.2 Q7.1(S) Q7.2(S) Q7.3(S) Q9.5(D) Q9.6(D) Q9.7(D) Q9.8(D) Q9.9(D) R154.1 U27.15(SP1)  [project net SP1_P1_17]
SP2_P1: NT6.2 Q12.1(S) Q12.2(S) Q12.3(S) Q14.5(D) Q14.6(D) Q14.7(D) Q14.8(D) Q14.9(D) R162.1 U27.17(SP2)  [project net SP2_P1_17]
SPI7_CS5: R158.2 U27.56(~{SCS}) ; port nCS_DRV8714
VCP: C101.2 U27.37(VCP)  [project net VCP_17]
NetC101_1: C101.1 R153.2 U27.38(PVDD)
NetC102_1: C102.1 U27.36(CP1H)
NetC102_2: C102.2 U27.35(CP1L)
NetC103_1: C103.1 U27.34(CP2H)
NetC103_2: C103.2 U27.33(CP2L)
NetQ7_4: Q7.4(G) R152.2
NetQ8_4: Q8.4(G) R151.1
NetQ9_4: Q9.4(G) R157.2
NetQ10_4: Q10.4(G) R156.1
NetQ11_4: Q11.4(G) R160.2
NetQ12_4: Q12.4(G) R161.2
NetQ13_4: Q13.4(G) R163.2
NetQ14_4: Q14.4(G) R164.2
NetR159_2: R159.2 U27.3(SDO)

Not connected (* = marked no-connect by the designer): U27 19(NC)* 20(NC)* 21(NC)* 29(NC)* 30(NC)* 31(NC)* 40(NC)* 41(NC)* 42(NC)* 43(NC)* 51(NC)* 52(NC)* 53(NC)*

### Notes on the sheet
- nSLEEP internal PD, active LO
- Recommended to pull-up CS for AM263P
- DNP Output Caps

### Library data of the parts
C96 = CMP-0860442-1: CAP, AL, 330 µF, 50 V, +/- 20%, 0.12 ohm, AEC-Q200 Grade 2, SMD; Manufacturer: Panasonic; ESR_ohm: 0.12; CompType: Capacitor; U/M: EA; AEC Qualified: Y; TaMax_C: 105°C; Green_Lifecycle: Active; SizeY_mm: 10.3; SizeZ_mm: 10.2; Value: 330uF; AEC Grade: 2; TaMin_C: -55°C; Green_REACh: Passed; SizeArea_mm2: 123.6; AEC Category: Q200; Cap_Case: 10x10.2mm; SizeAreaWB_mm2: 172.2; SizeX_mm: 12
C97 C98 C108 C109 = CMP-0007696-2: CAP, CERM, 1 uF, 50 V, +/- 10%, X7R, 0805; Manufacturer: Wurth Elektronik; TaMin_C: -55°C; Polarized: N; SizeAreaWB_mm2: 6.75; Value1: Unknown; U/M: EA; Value: 1uF; TaMax_C: 125°C; SizeZ_mm: 1.45; SizeX_mm: 2; SizeY_mm: 1.25; Cap_Case: 0805; SizeArea_mm2: 2.5; Cap_F: 1µF; AEC Category: Q200
C99 = CMP-0009164-2: CAP, CERM, 10 uF, 50 V, +/- 10%, X7S, AEC-Q200 Grade 1, 1210; Manufacturer: TDK; TaMin_C: -55°C; ESR_ohm: 2.827m; Polarized: N; SizeAreaWB_mm2: 14.7; Value1: 0.002827 ohm; U/M: EA; Value: 10uF; TaMax_C: 125°C; SizeZ_mm: 2.8; SizeX_mm: 3.2; SizeY_mm: 2.5; SizeArea_mm2: 8; AEC Qualified: Y; Cap_F: 10µF; IRMS_A: 4.37286A; AEC Grade: 1; AEC Category: Q200
C100 C102 C103 = CMP-0006837-4: CAP, CERM, 0.1 uF, 50 V, +/- 10%, X7R, 0603; Manufacturer: Wurth Elektronik; TaMin_C: -55°C; Polarized: N; SizeAreaWB_mm2: 4.68; Value1: Unknown; U/M: EA; Value: 0.1uF; TaMax_C: 125°C; SizeZ_mm: 1; SizeX_mm: 1.6; SizeY_mm: 0.8; Cap_Case: 0603; SizeArea_mm2: 1.28; Cap_F: 100nF; AEC Category: Q200
C101 = CMP-0006831-4: CAP, CERM, 1 uF, 16 V, +/- 10%, X7R, 0603; Manufacturer: Wurth Elektronik; TaMin_C: -55°C; Polarized: N; SizeAreaWB_mm2: 4.68; Value1: Unknown; U/M: EA; Value: 1uF; TaMax_C: 125°C; SizeZ_mm: 1; SizeX_mm: 1.6; SizeY_mm: 0.8; Cap_Case: 0603; SizeArea_mm2: 1.28; Cap_F: 1µF; AEC Category: Q200
C104 C107 C110 C111 = CMP-0079095-1: as C78 on sheet High Side Switches
C105 = CMP-0095056-1: Cap Ceramic 1uF 6.3V X7R 5% Pad SMD 0603 Flexible Termination 125°C Automotive T/R; Manufacturer: KEMET; AEC Grade: Grade 1; Value: 1µF; SizeZ_mm: 0.95mm; AEC Qualified: Yes; TempCo: 15%
C106 = CMP-0086271-1: CAP, CERM, 0.1 µF, 6.3 V,+/- 10%, X7R, 0603; Manufacturer: Kemet; AEC Category: Q200; Cap_F: 100nF; Polarized: N; SizeArea_mm2: 1.28; TaMax_C: 125°C; SizeY_mm: 0.8; Value: 0.1uF; SizeAreaWB_mm2: 4.68; SizeZ_mm: 1; Cap_Case: 0603; SizeX_mm: 1.6; U/M: EA; TaMin_C: -55°C
NT1-NT6 = CMP-0078142-3: Single point connection between nets.
Q7-Q14 = CMP-0000713-2: MOSFET, N-CH, 40 V, 100 A, DNK0008A (VSON-CLIP-8); Alternate Manufacturer: None; Manufacturer: Texas Instruments; SizeZ_mm: 1; ChType: N; Value2: 37 nC; Value1: 0.002; VdsMax_V: 40V; SizeX_mm: 6; SizeY_mm: 5; Vgs_V: 20V; Value: 40V; Rdson45_ohm: 2.3m; SizeArea_mm2: 30; AEC Category: Q101; IdsMax_A: 100A; SizeAreaWB_mm2: 56; U/M: EA; QgTyp_nC: 37
R150-R152 R156 R157 R160 R161 R163 R164 = CMP-0025697-4: RES, 0, 5%, 0.1 W, AEC-Q200 Grade 0, 0603; PartNumber: CRCW06030000Z0EA; Manufacturer: Vishay-Dale; Value_Code: 0000; Power_W: 100mW; Value2: 0.1W; VDC_V: 75V; TempCo: 200 ppm/C; EIA_Code: E24; AEC Category: Q200; AEC Qualified: Y; SizeArea_mm2: 1.28; SizeX_mm: 1.6; SizeY_mm: 0.8; SizeZ_mm: 1
R153 = CMP-0026822-1: RES, 0, 5%, 0.063 W, 0402; Manufacturer: Vishay-Dale; Power_W: 63mW; TempCo: 200 ppm/C; Value_Code: 0000; U/M: EA; Value: 0; EIA_Code: E24; SizeX_mm: 1; SizeY_mm: 0.5; SizeZ_mm: 0.6; Value2: 0.063W; VDC_V: 50V; AEC Category: Q200
R154 R162 = CMP-0086254-1: RES, 0.007, 1%, 7 W, AEC-Q200 Grade 0, 7.1x4.6mm; Manufacturer: Vishay-Dale; Res_ohm: 7m; EIA_Code: E96; Power_W: 7W; SizeArea_mm2: 32.2; SizeAreaWB_mm2: 59.4; SizeY_mm: 4.6; Value_Code: 7L000; AEC Category: Q200; SizeX_mm: 7; TempCo: 75 ppm/C; Value: 0.007; AEC Grade: 0; AEC Qualified: Y; SizeZ_mm: 1.75
R155 = CMP-0086251-1: RES, 10.0 k, 0.05%, 0.1 W, AEC-Q200 Grade 0, 0603; Manufacturer: Panasonic; Res_ohm: 10k; Value: 10.0k; SizeY_mm: 0.8; SizeArea_mm2: 1.28; SizeAreaWB_mm2: 4.68; AEC Grade: 0; Power_W: 100mW; SizeX_mm: 1.6; Value2: 0.1W; Value_Code: 10k0; SizeZ_mm: 1; AEC Qualified: Y; AEC Category: Q200; TempCo: 10 ppm/C
R158 = CMP-0094798-1: Res Thick Film 0402 10K Ohm 5% 0.063W(1/16W) ±100ppm/C Pad SMD T/R; Manufacturer: YAGEO; AEC Qualified: No; Category Cd01000Bfc2916C6: Single Components; SizeZ_mm: 0.4mm; VDC_V: 50V; Category 5C6A91606D4187Ad: Resistors; TempCo: 100ppm/°C; Power_W: 63mW; Category 7542B8484461Ae85: Passive Components
R159 = CMP-0027500-1: RES, 22.0, 1%, 0.05 W, 0201; Manufacturer: Yageo America; Power_W: 50mW; TempCo: 200 ppm/C; Value_Code: 22R0; U/M: EA; Value: 22.0; Res_ohm: 22; SizeX_mm: 0.6; SizeY_mm: 0.3; SizeZ_mm: 0.26; Value2: 0.05W; SizeArea_mm2: 0.18; AEC Qualified: N; VDC_V: 25V; AEC Category: Q200
U27 = CMP-0860746-6: Automotive Multi-Channel Smart Half-Bridge Gate Drivers With Wide Common Mode Current Sense Amplifiers, RVJ0056A (VQFN-56); Alternate Manufacturer: Texas Instruments; CompType: IC; SizeZ_mm: 1; SizeAreaWB_mm2: 100; AEC Qualified: Y; AEC Category: Q200; SizeArea_mm2: 64; SizeY_mm: 8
